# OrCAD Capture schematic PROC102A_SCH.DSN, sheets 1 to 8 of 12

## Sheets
1 12.HARDWARE SCHEMATIC: title: HARDWARE SCHEMATIC; rev: E1
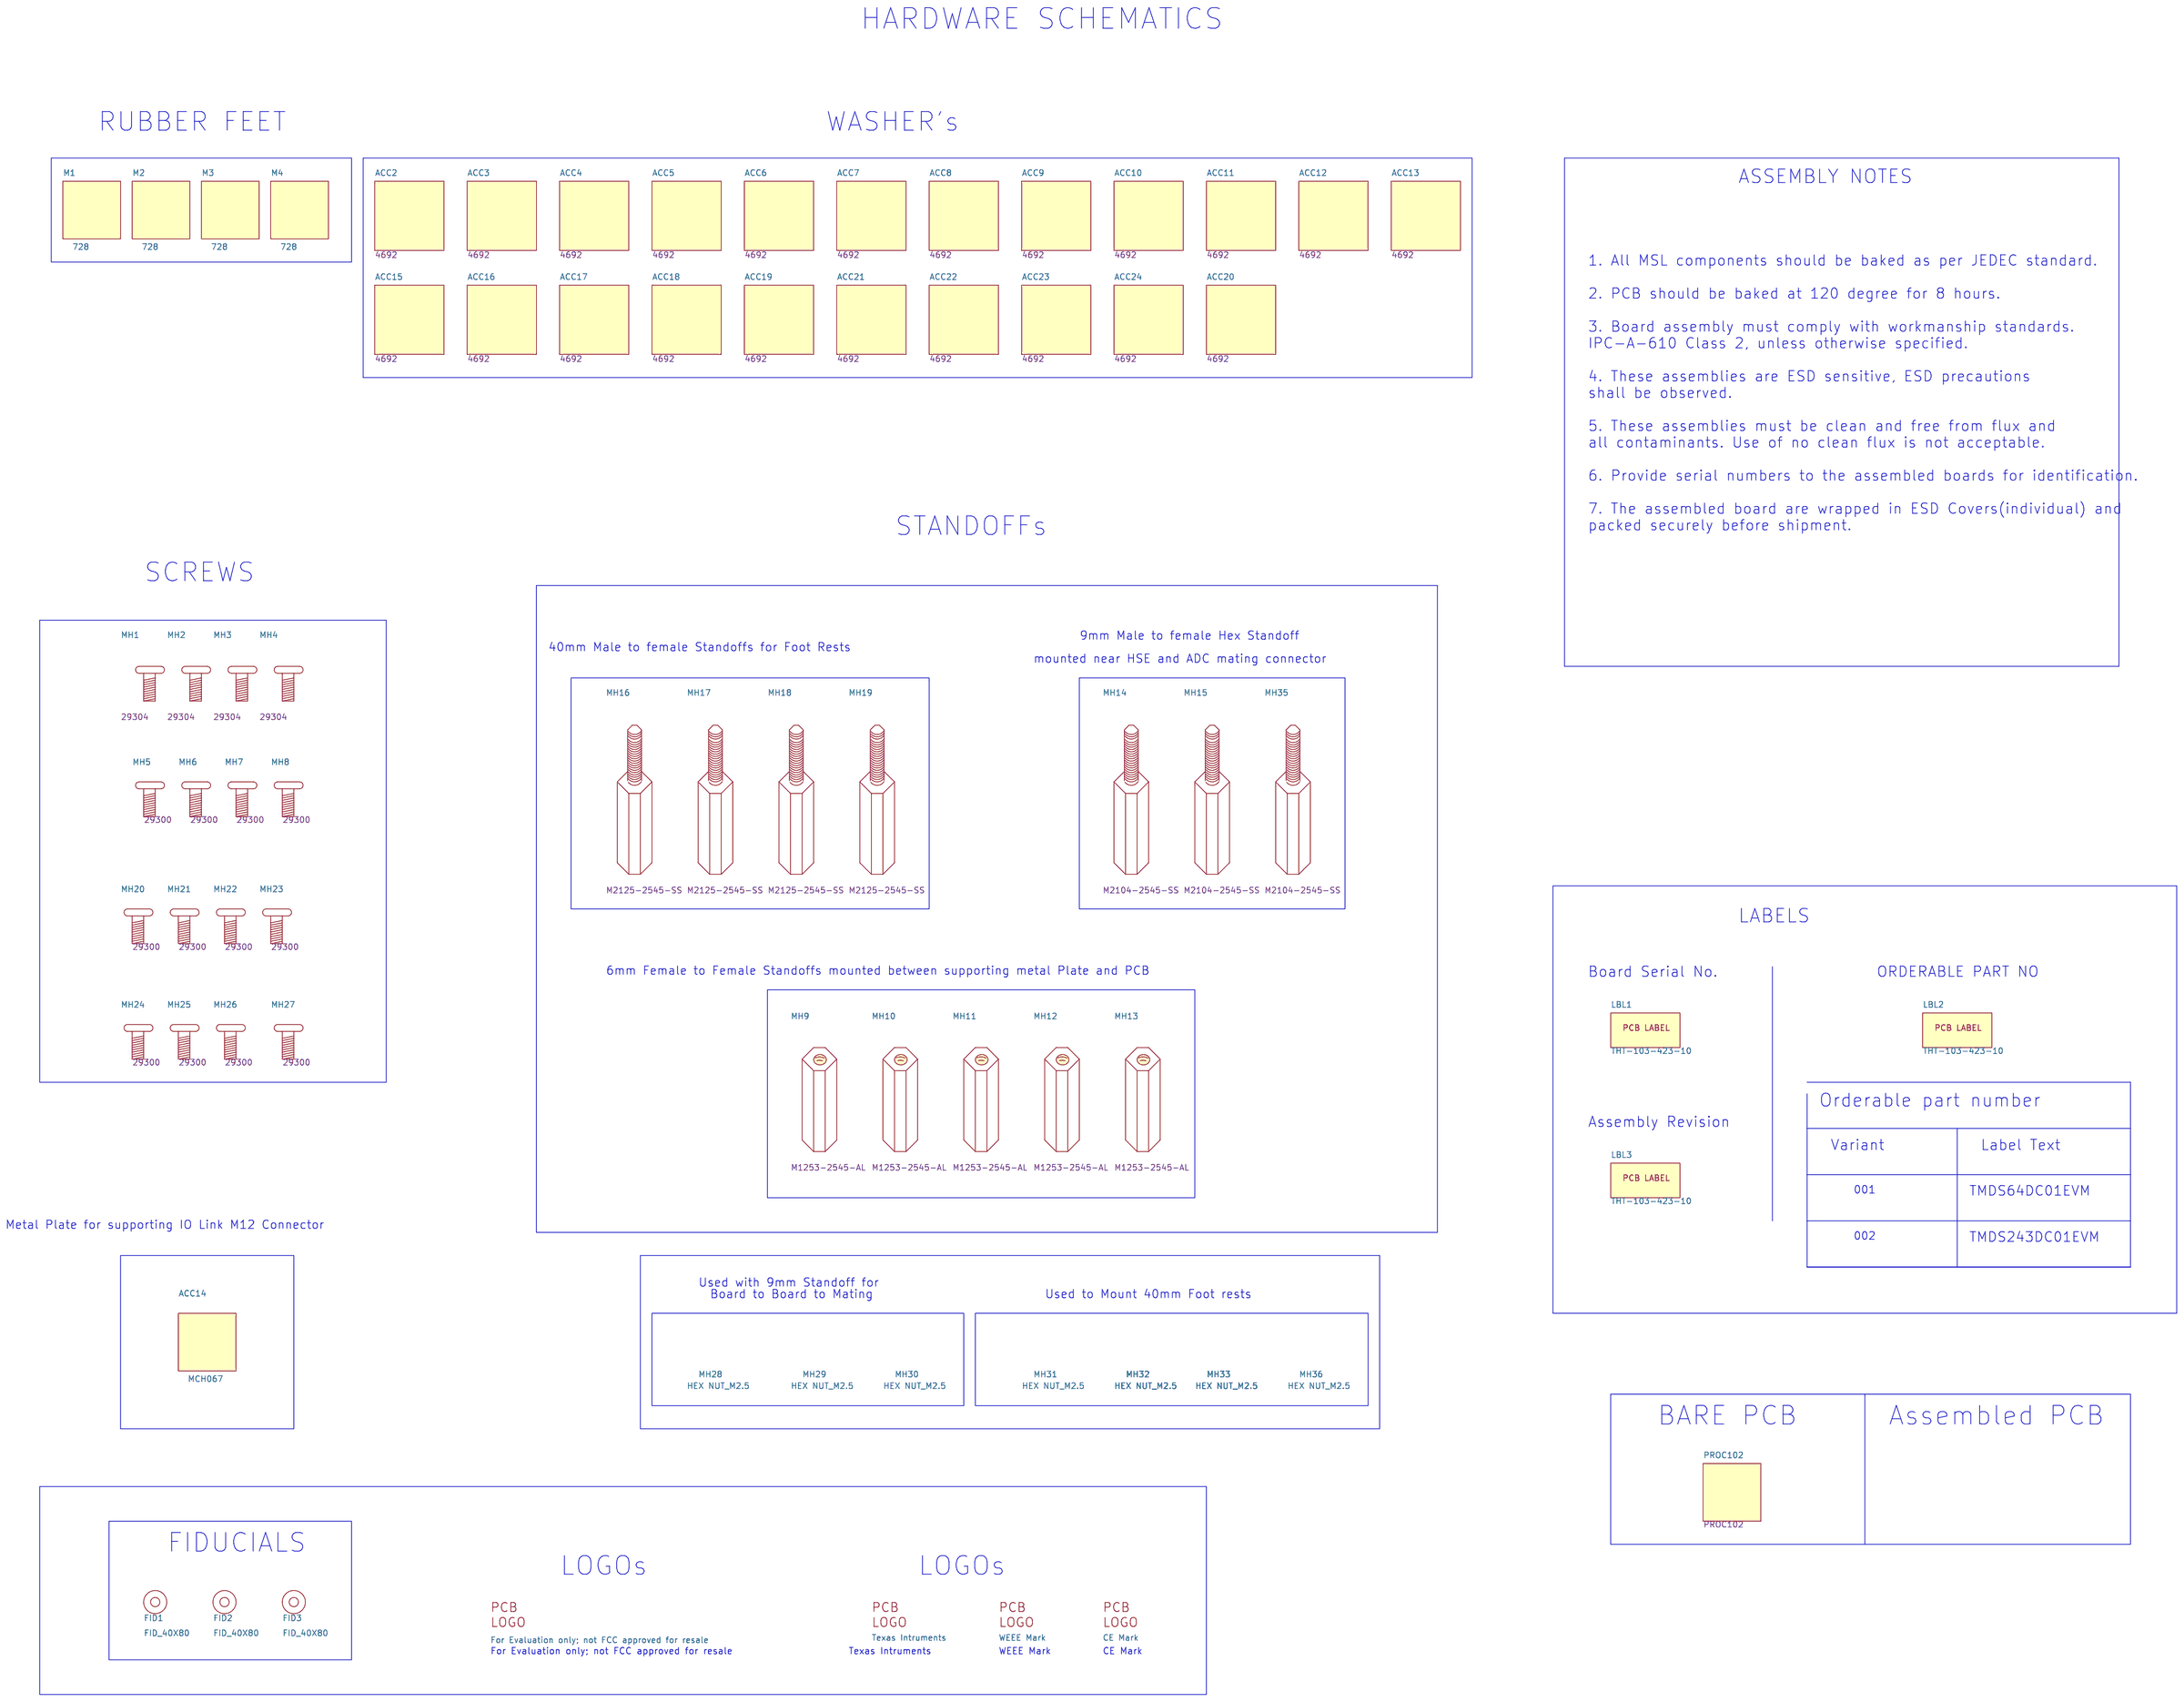
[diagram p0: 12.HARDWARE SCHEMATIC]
2 01.TABLE OF CONTENTS: title: TABLE OF CONTENTS
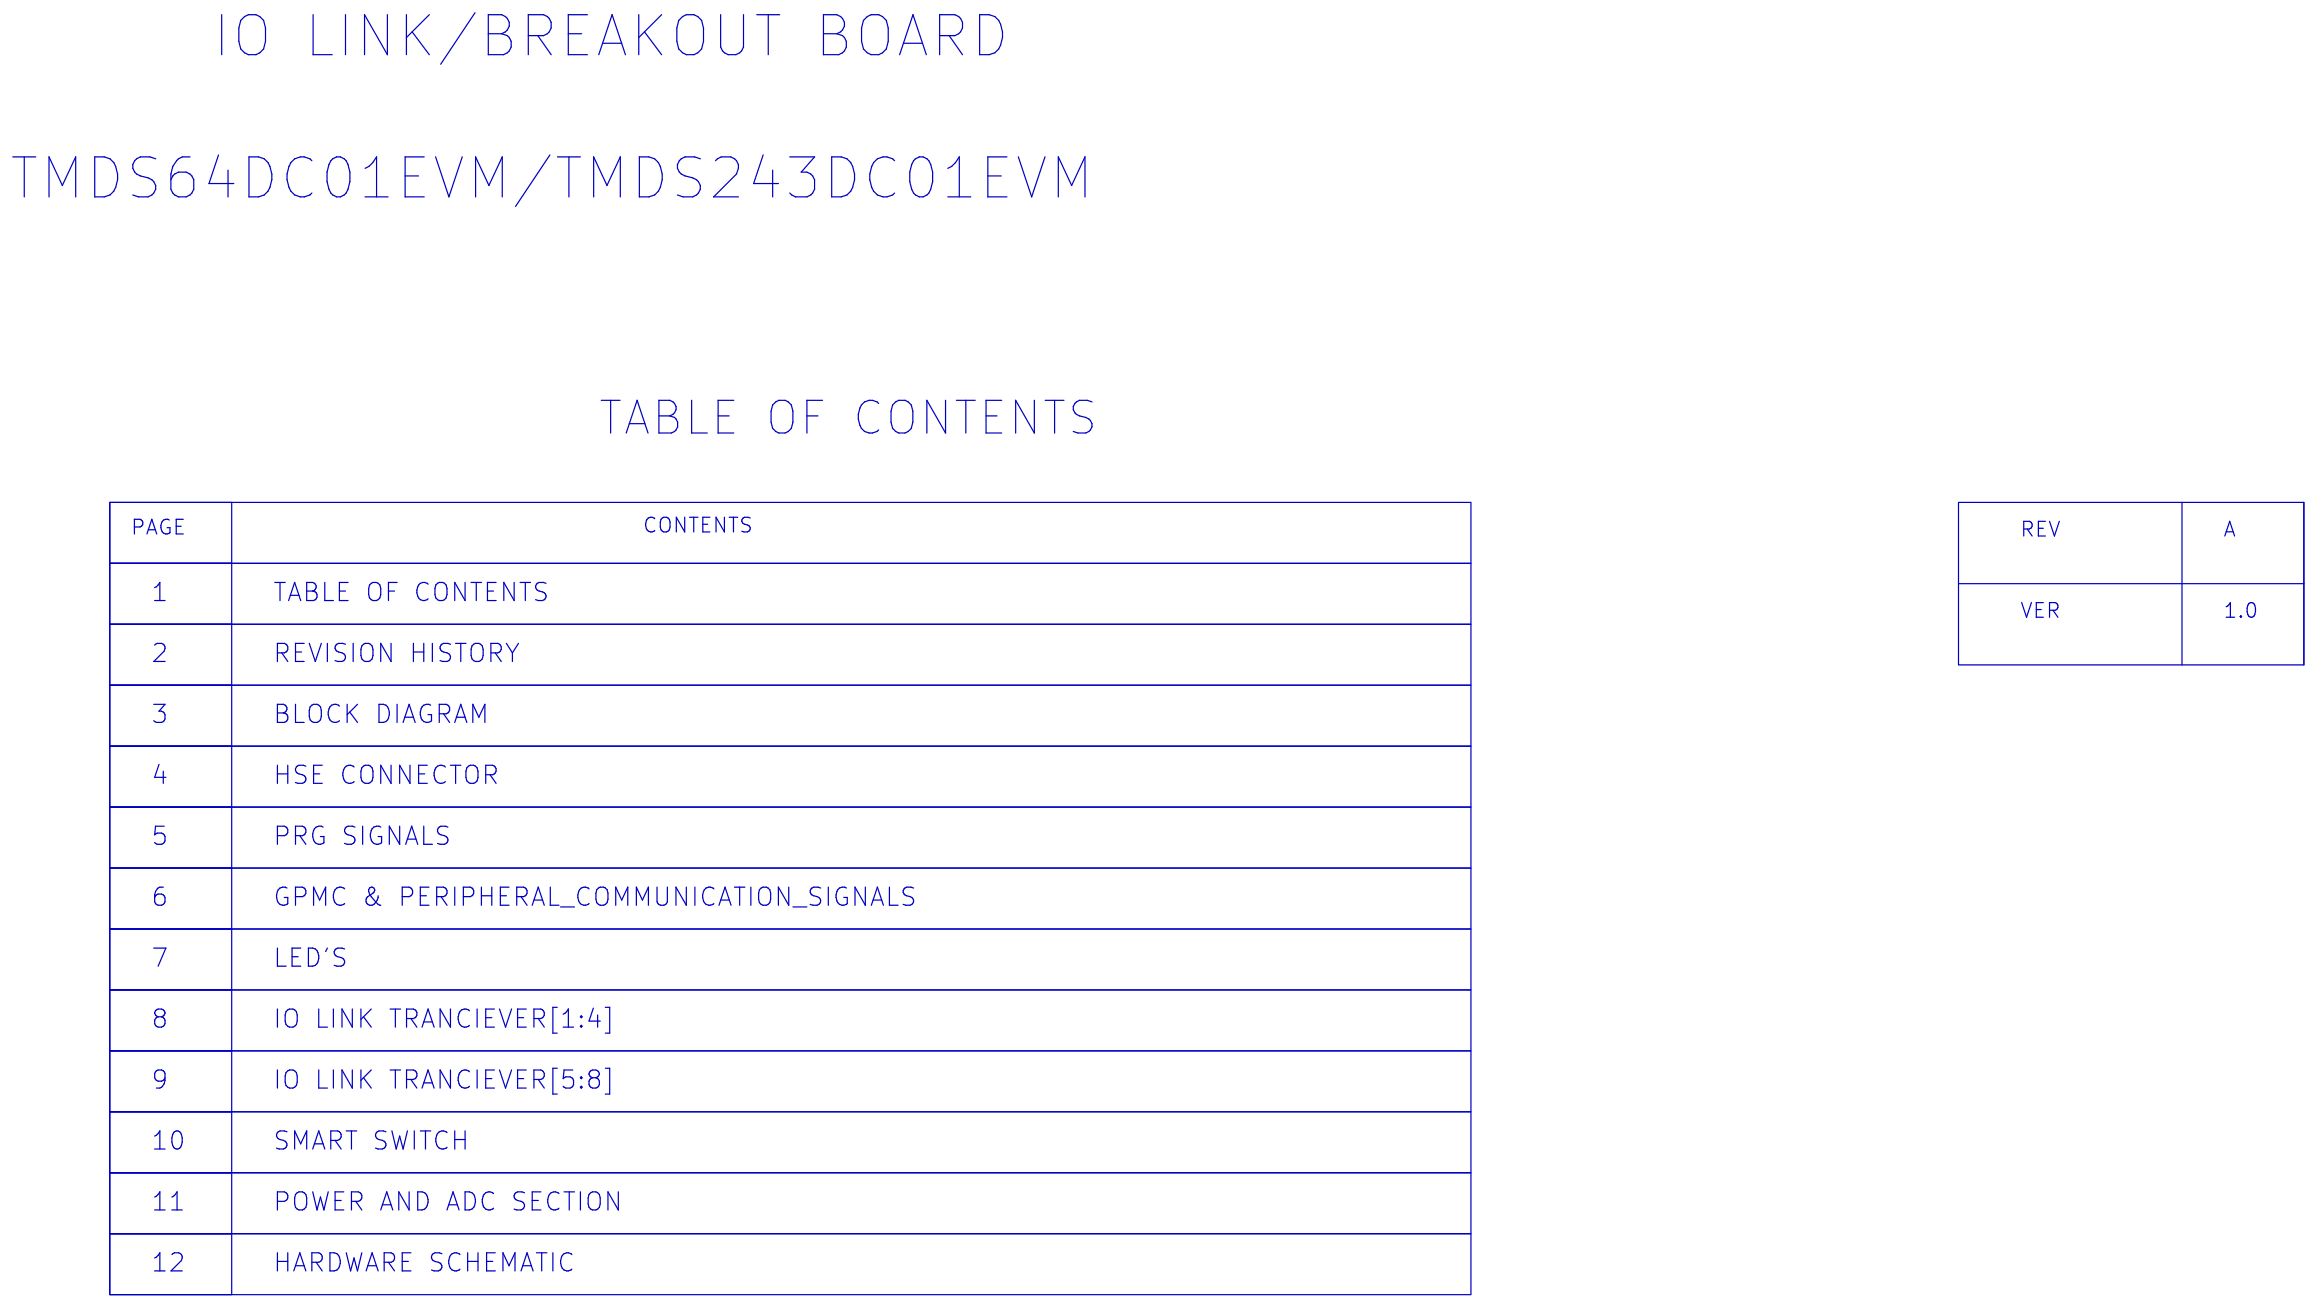
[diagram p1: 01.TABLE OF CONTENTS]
3 02.REVISION HISTORY: title: REV HISTORY
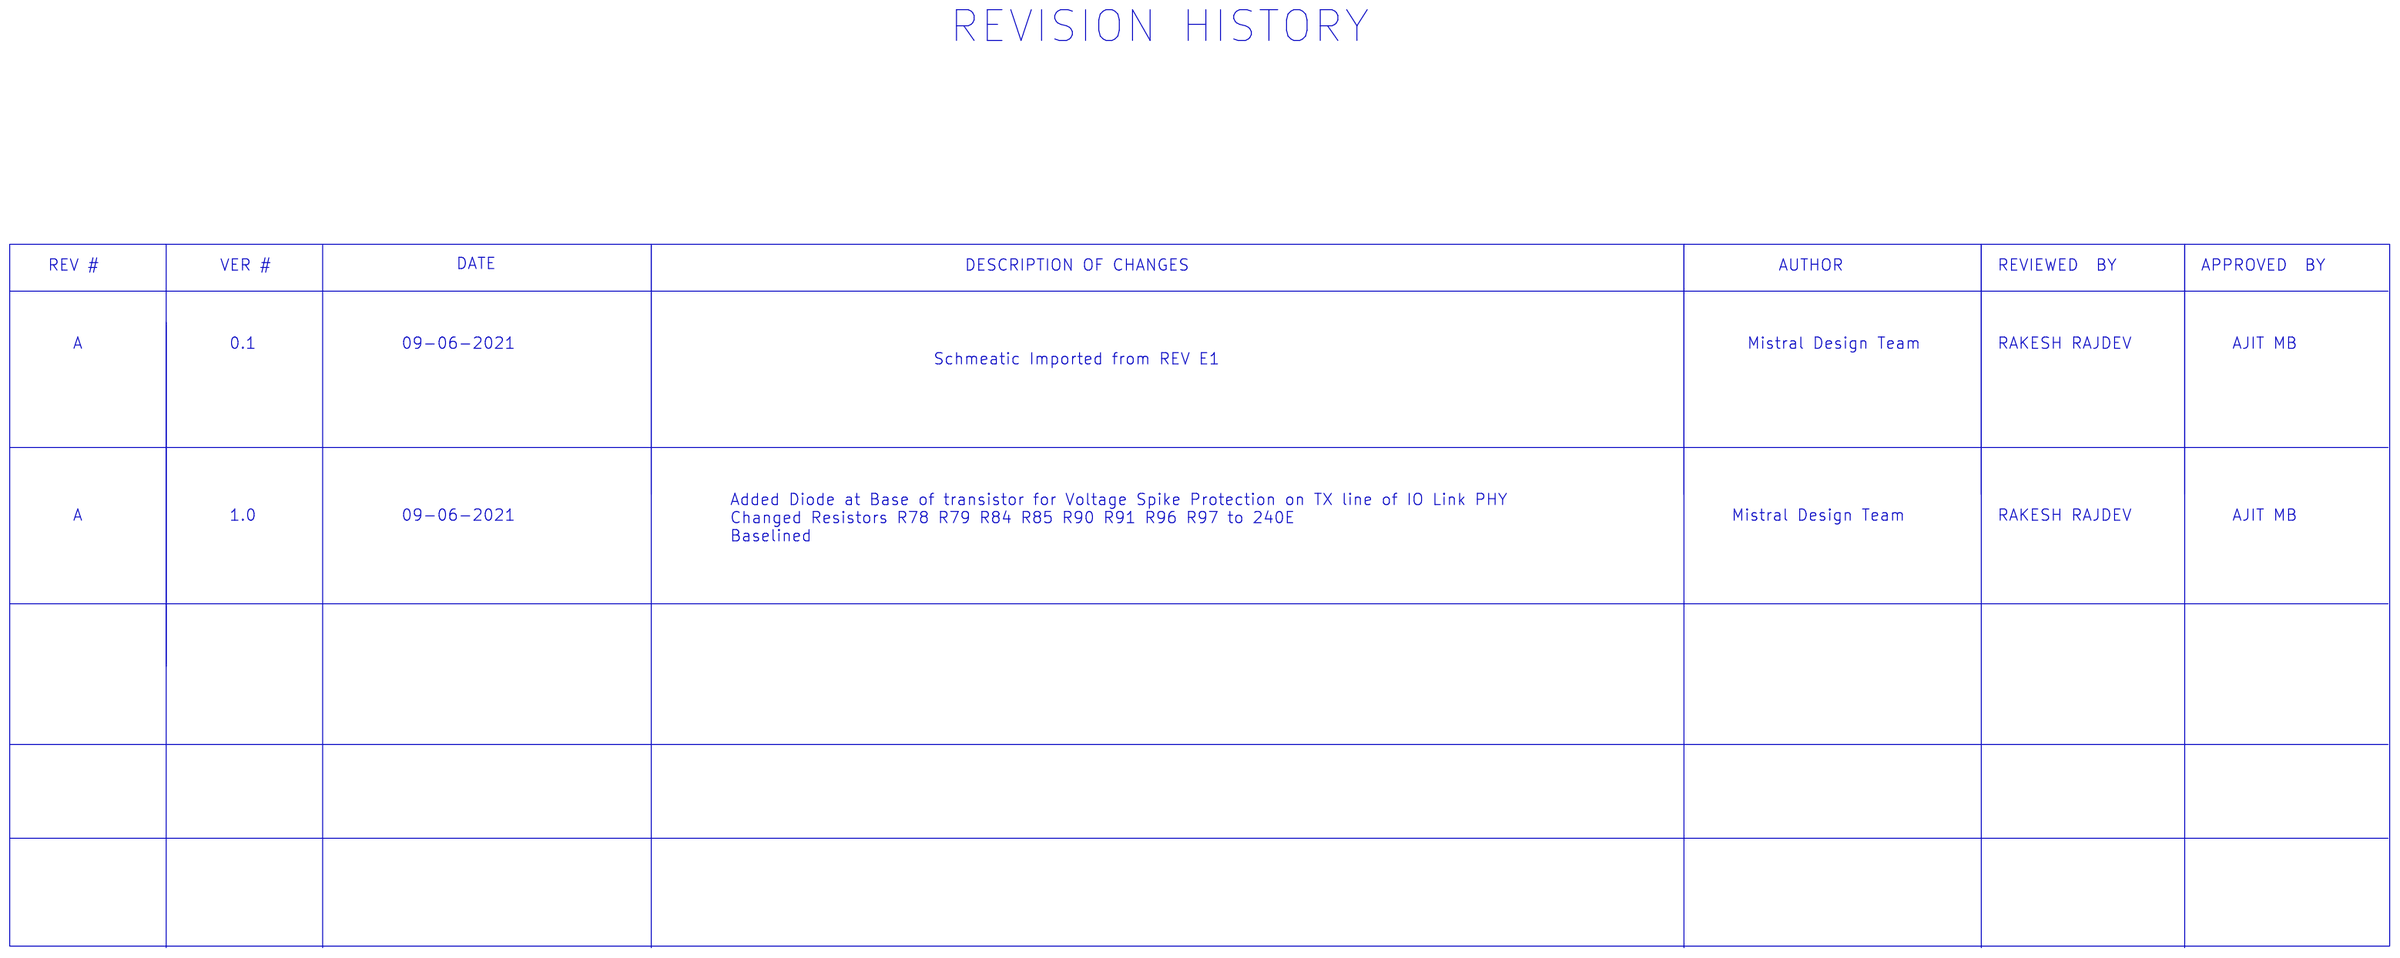
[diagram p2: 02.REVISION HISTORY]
4 03.BLOCK DIAGRAM: title: BLOCK DIAGRAM
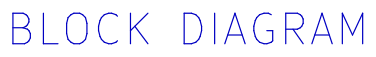
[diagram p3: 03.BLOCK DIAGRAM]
5 04.HSE CONNECTOR: size C; title: HSE CONNECTOR
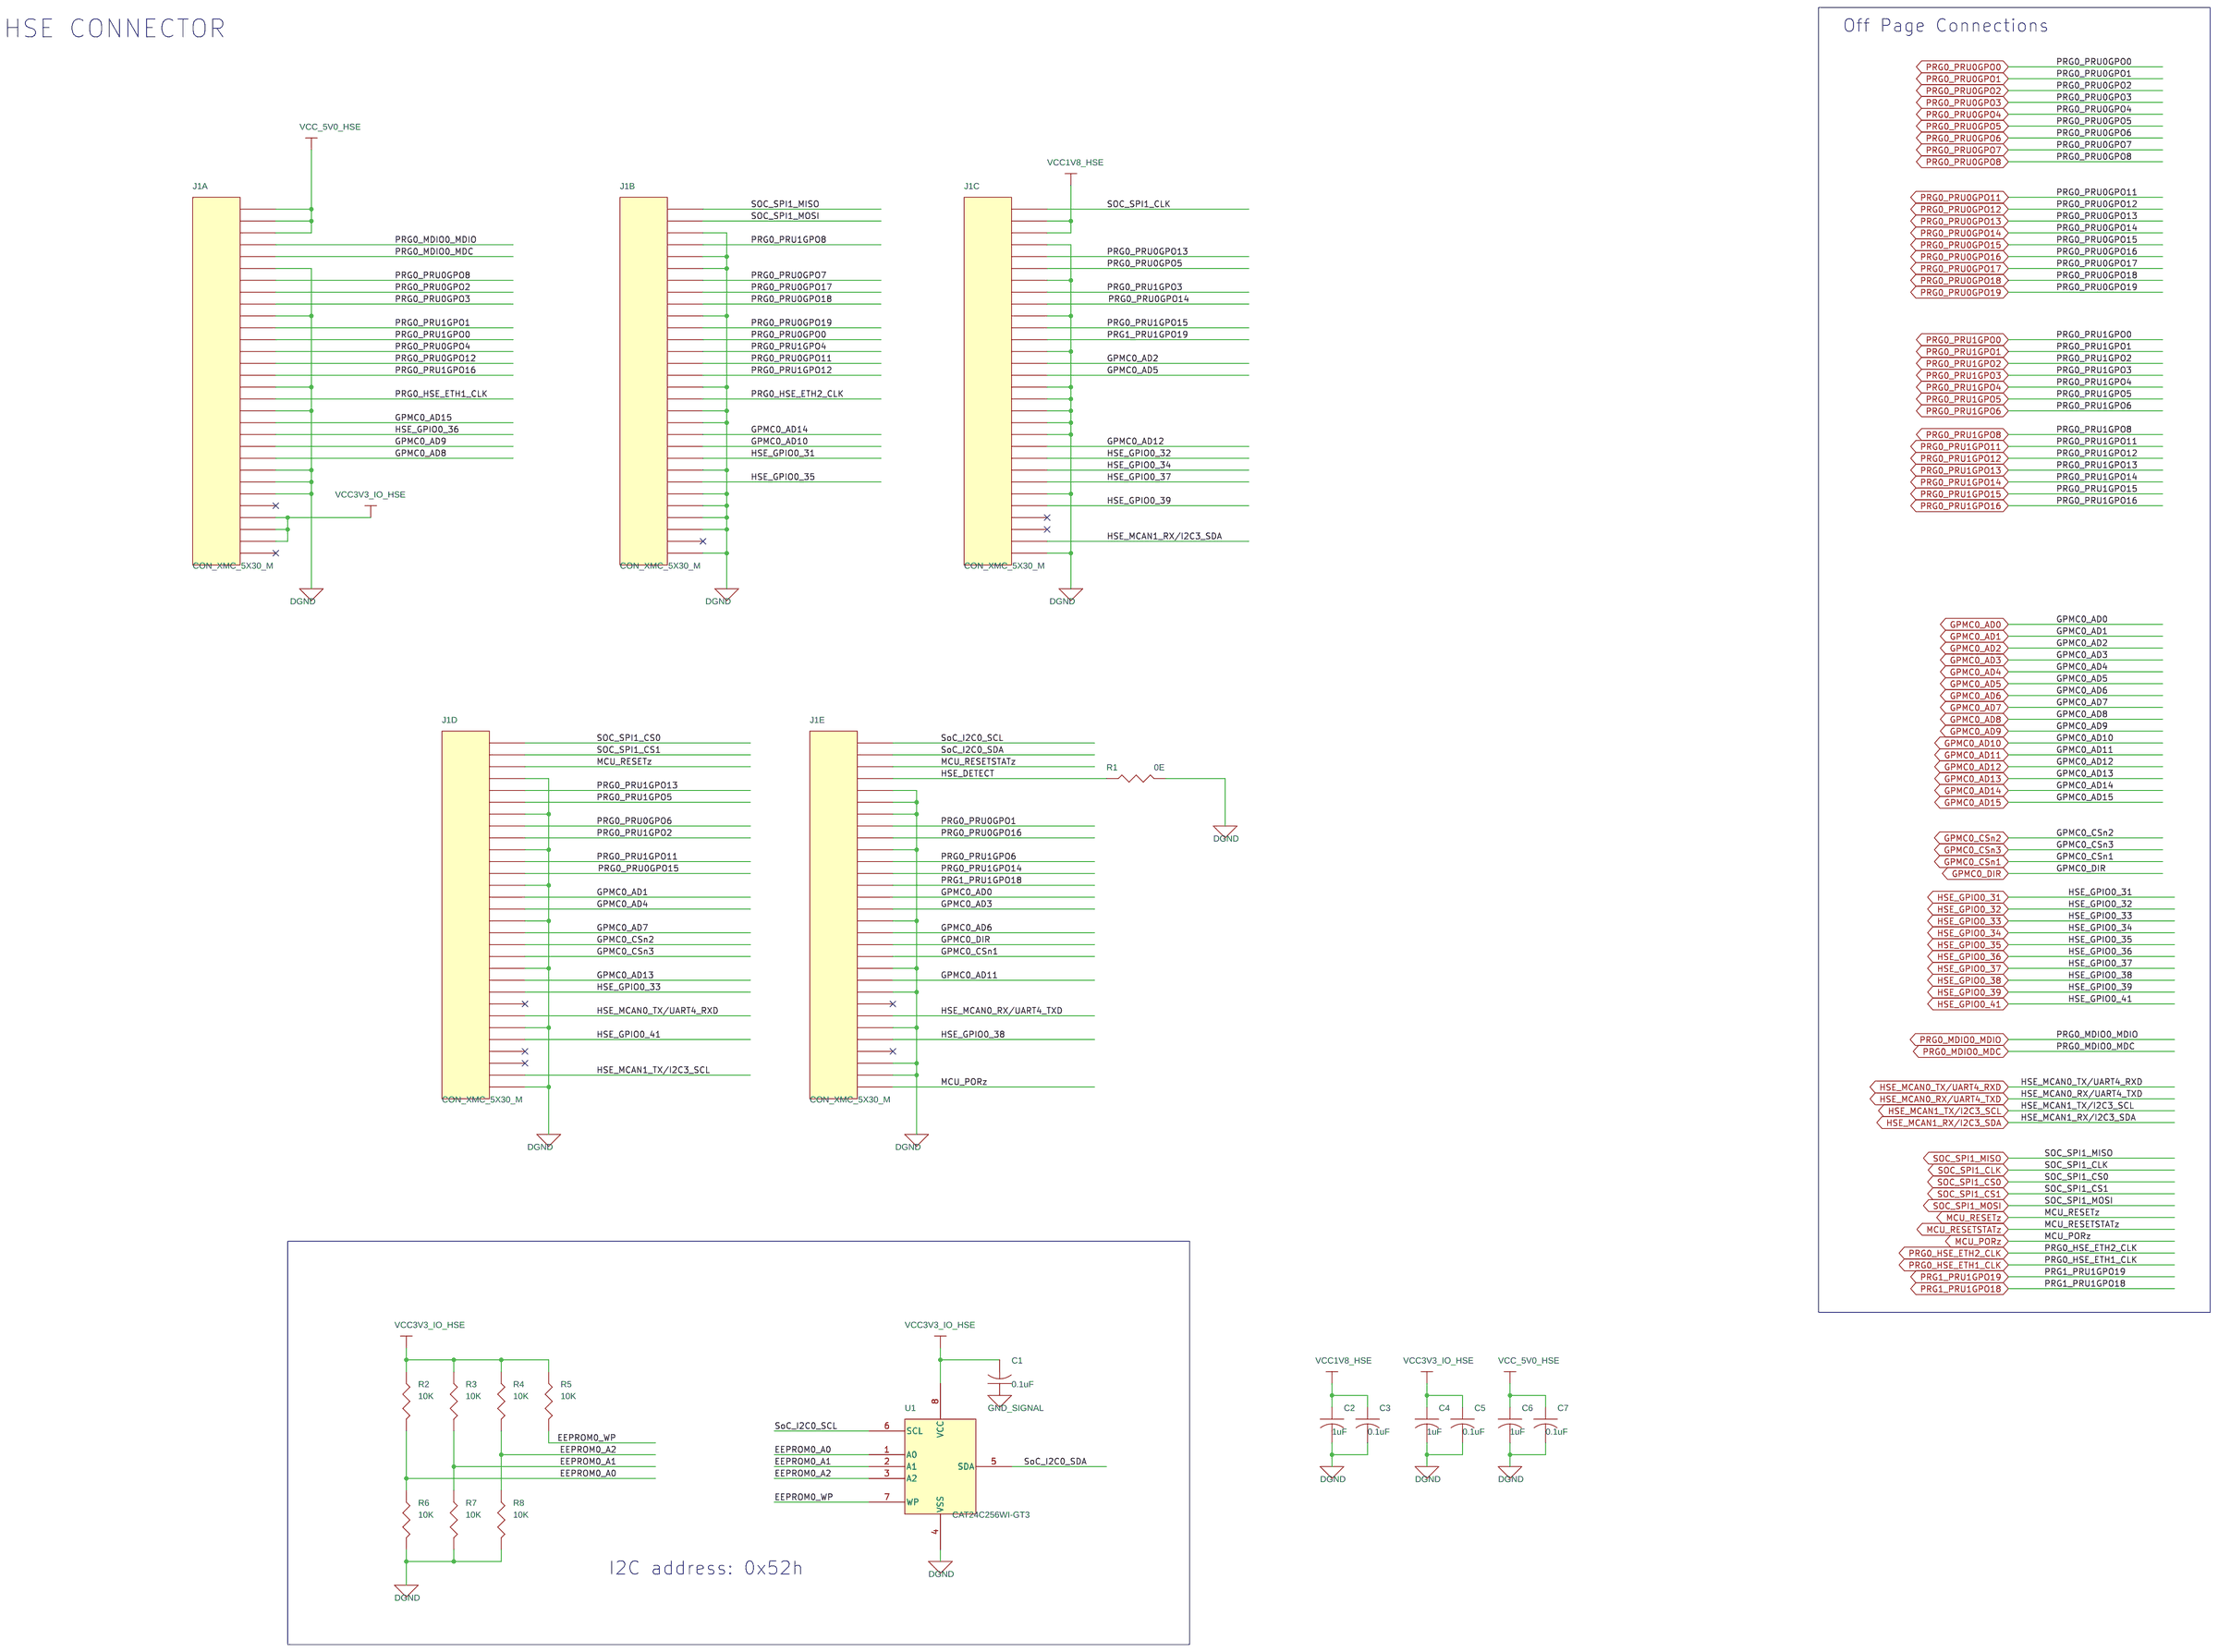
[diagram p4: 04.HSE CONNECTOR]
6 05.PRGO SIGNALS(01): size C; title: PRG SIGNALS
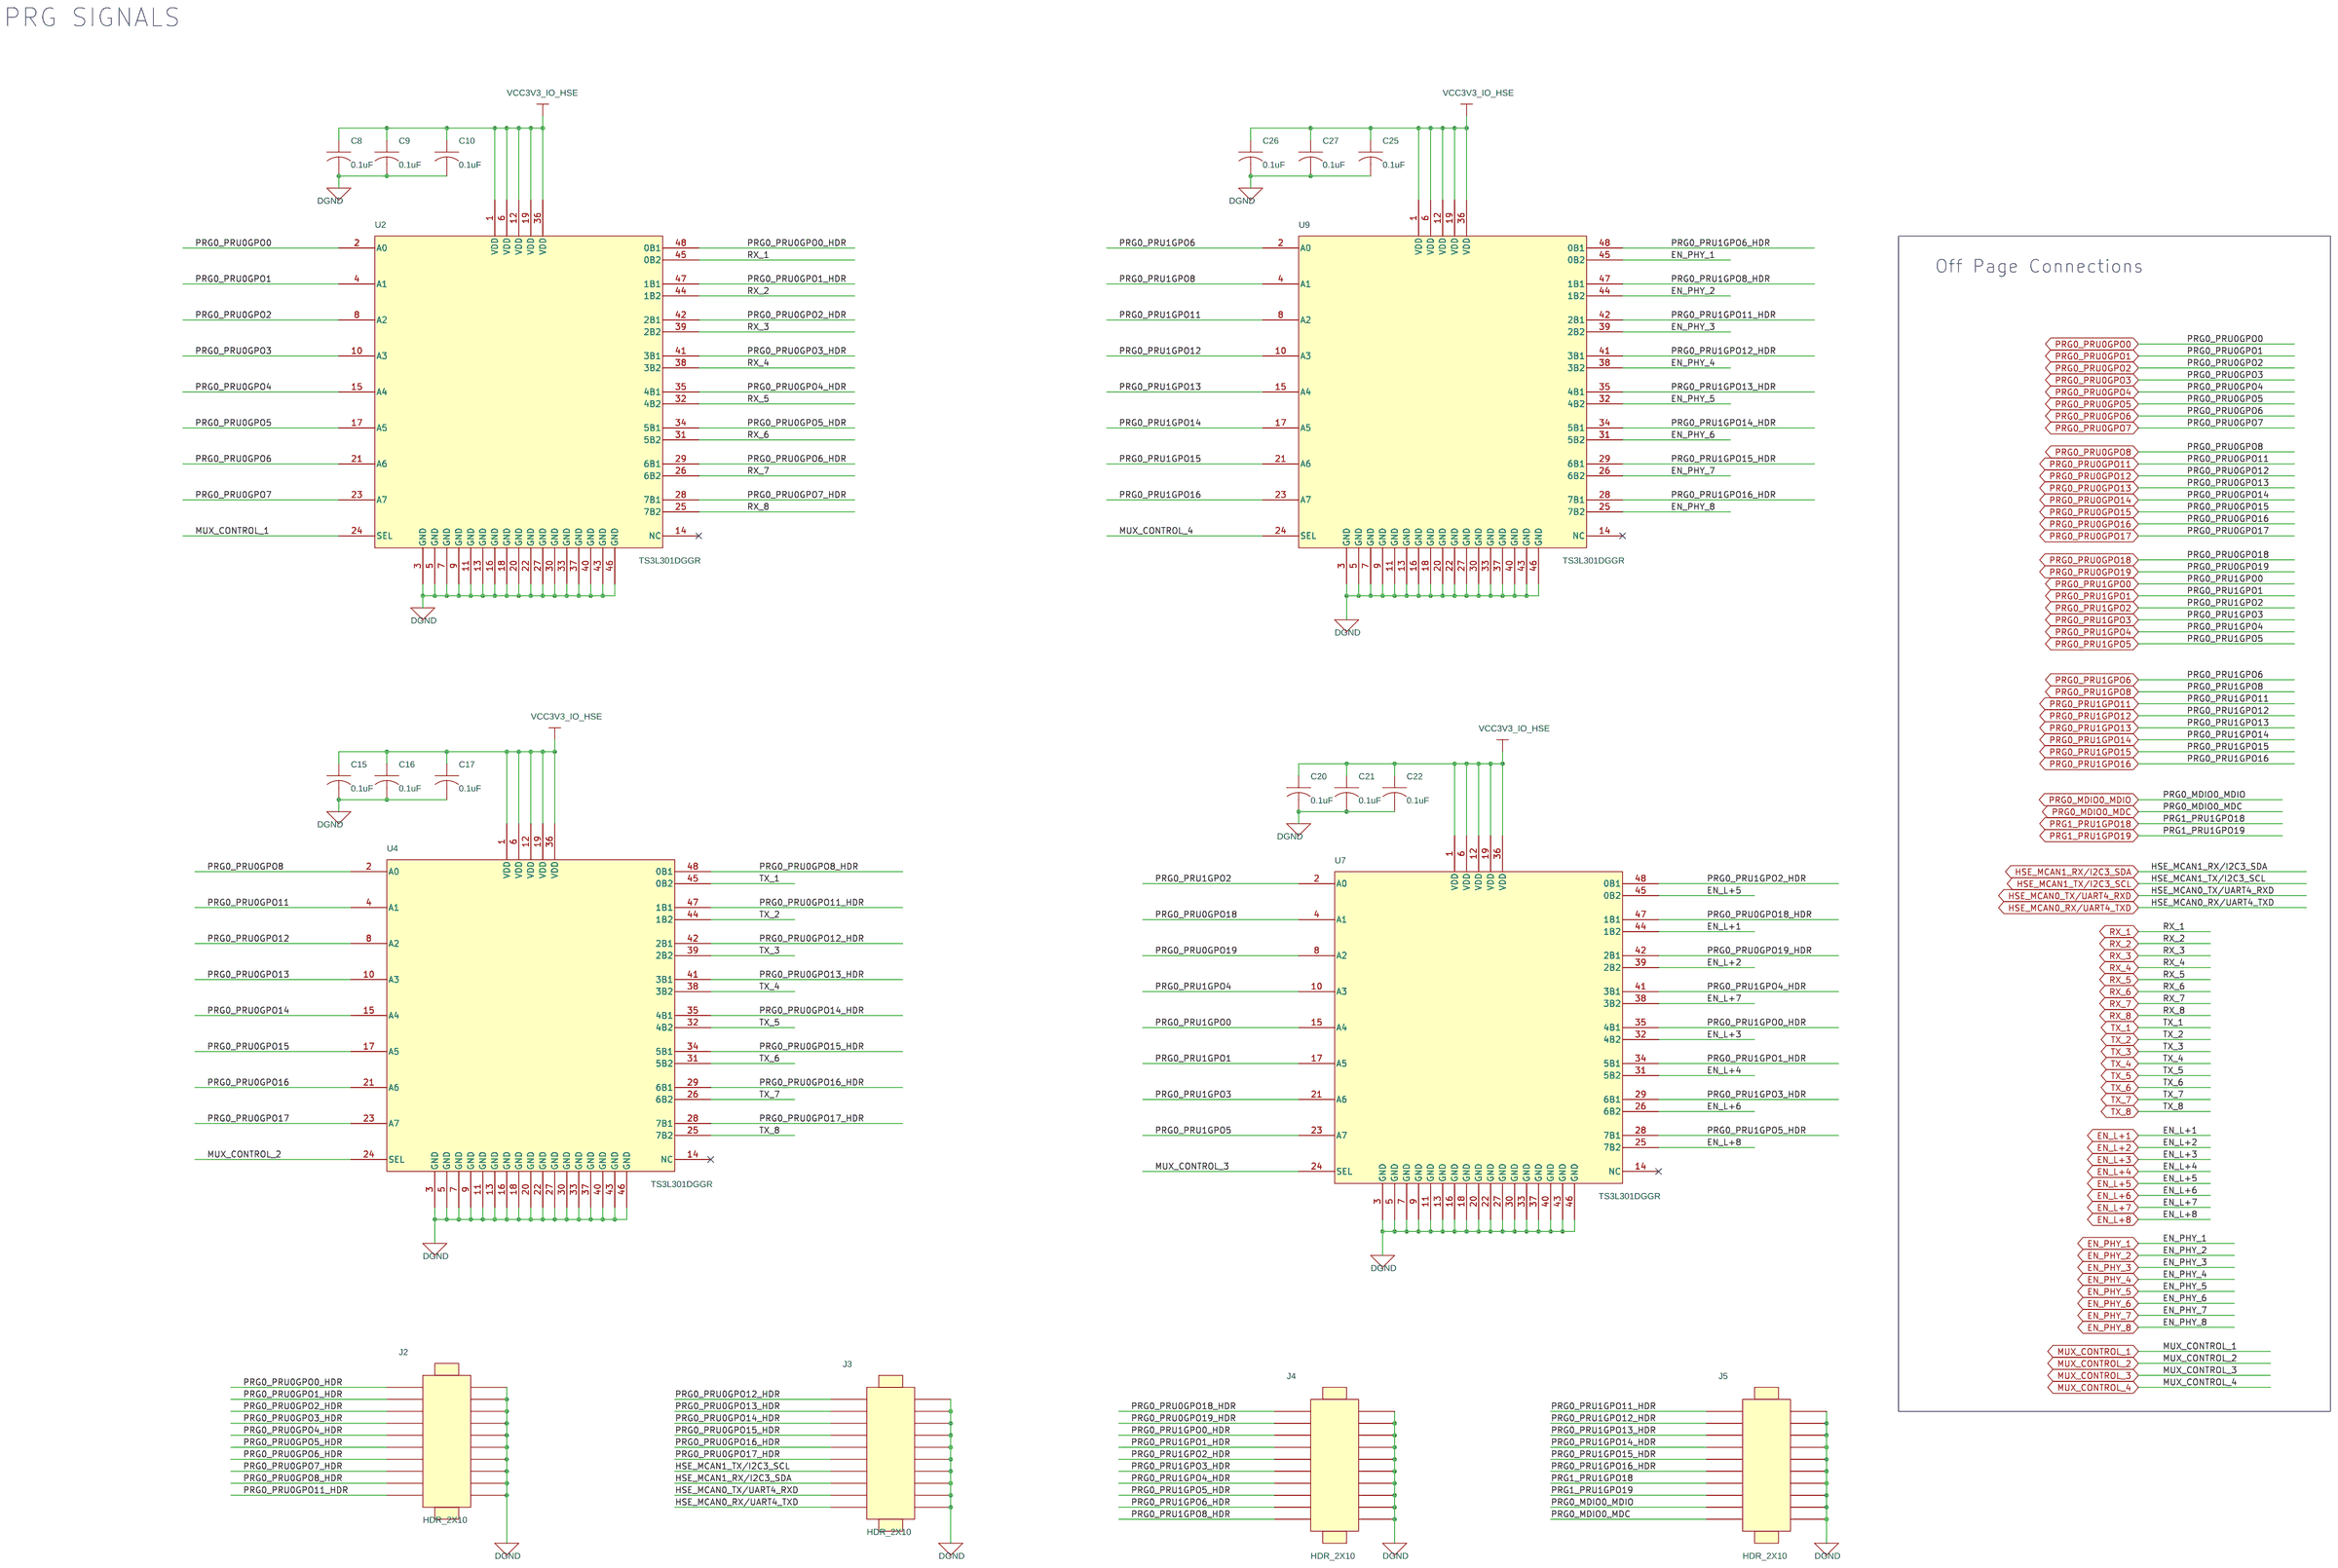
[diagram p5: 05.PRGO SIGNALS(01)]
7 06.PRG0 SIGNAL(02): size C; title: GPMC & PERIPHERAL COMMUNICATION SIGNALS
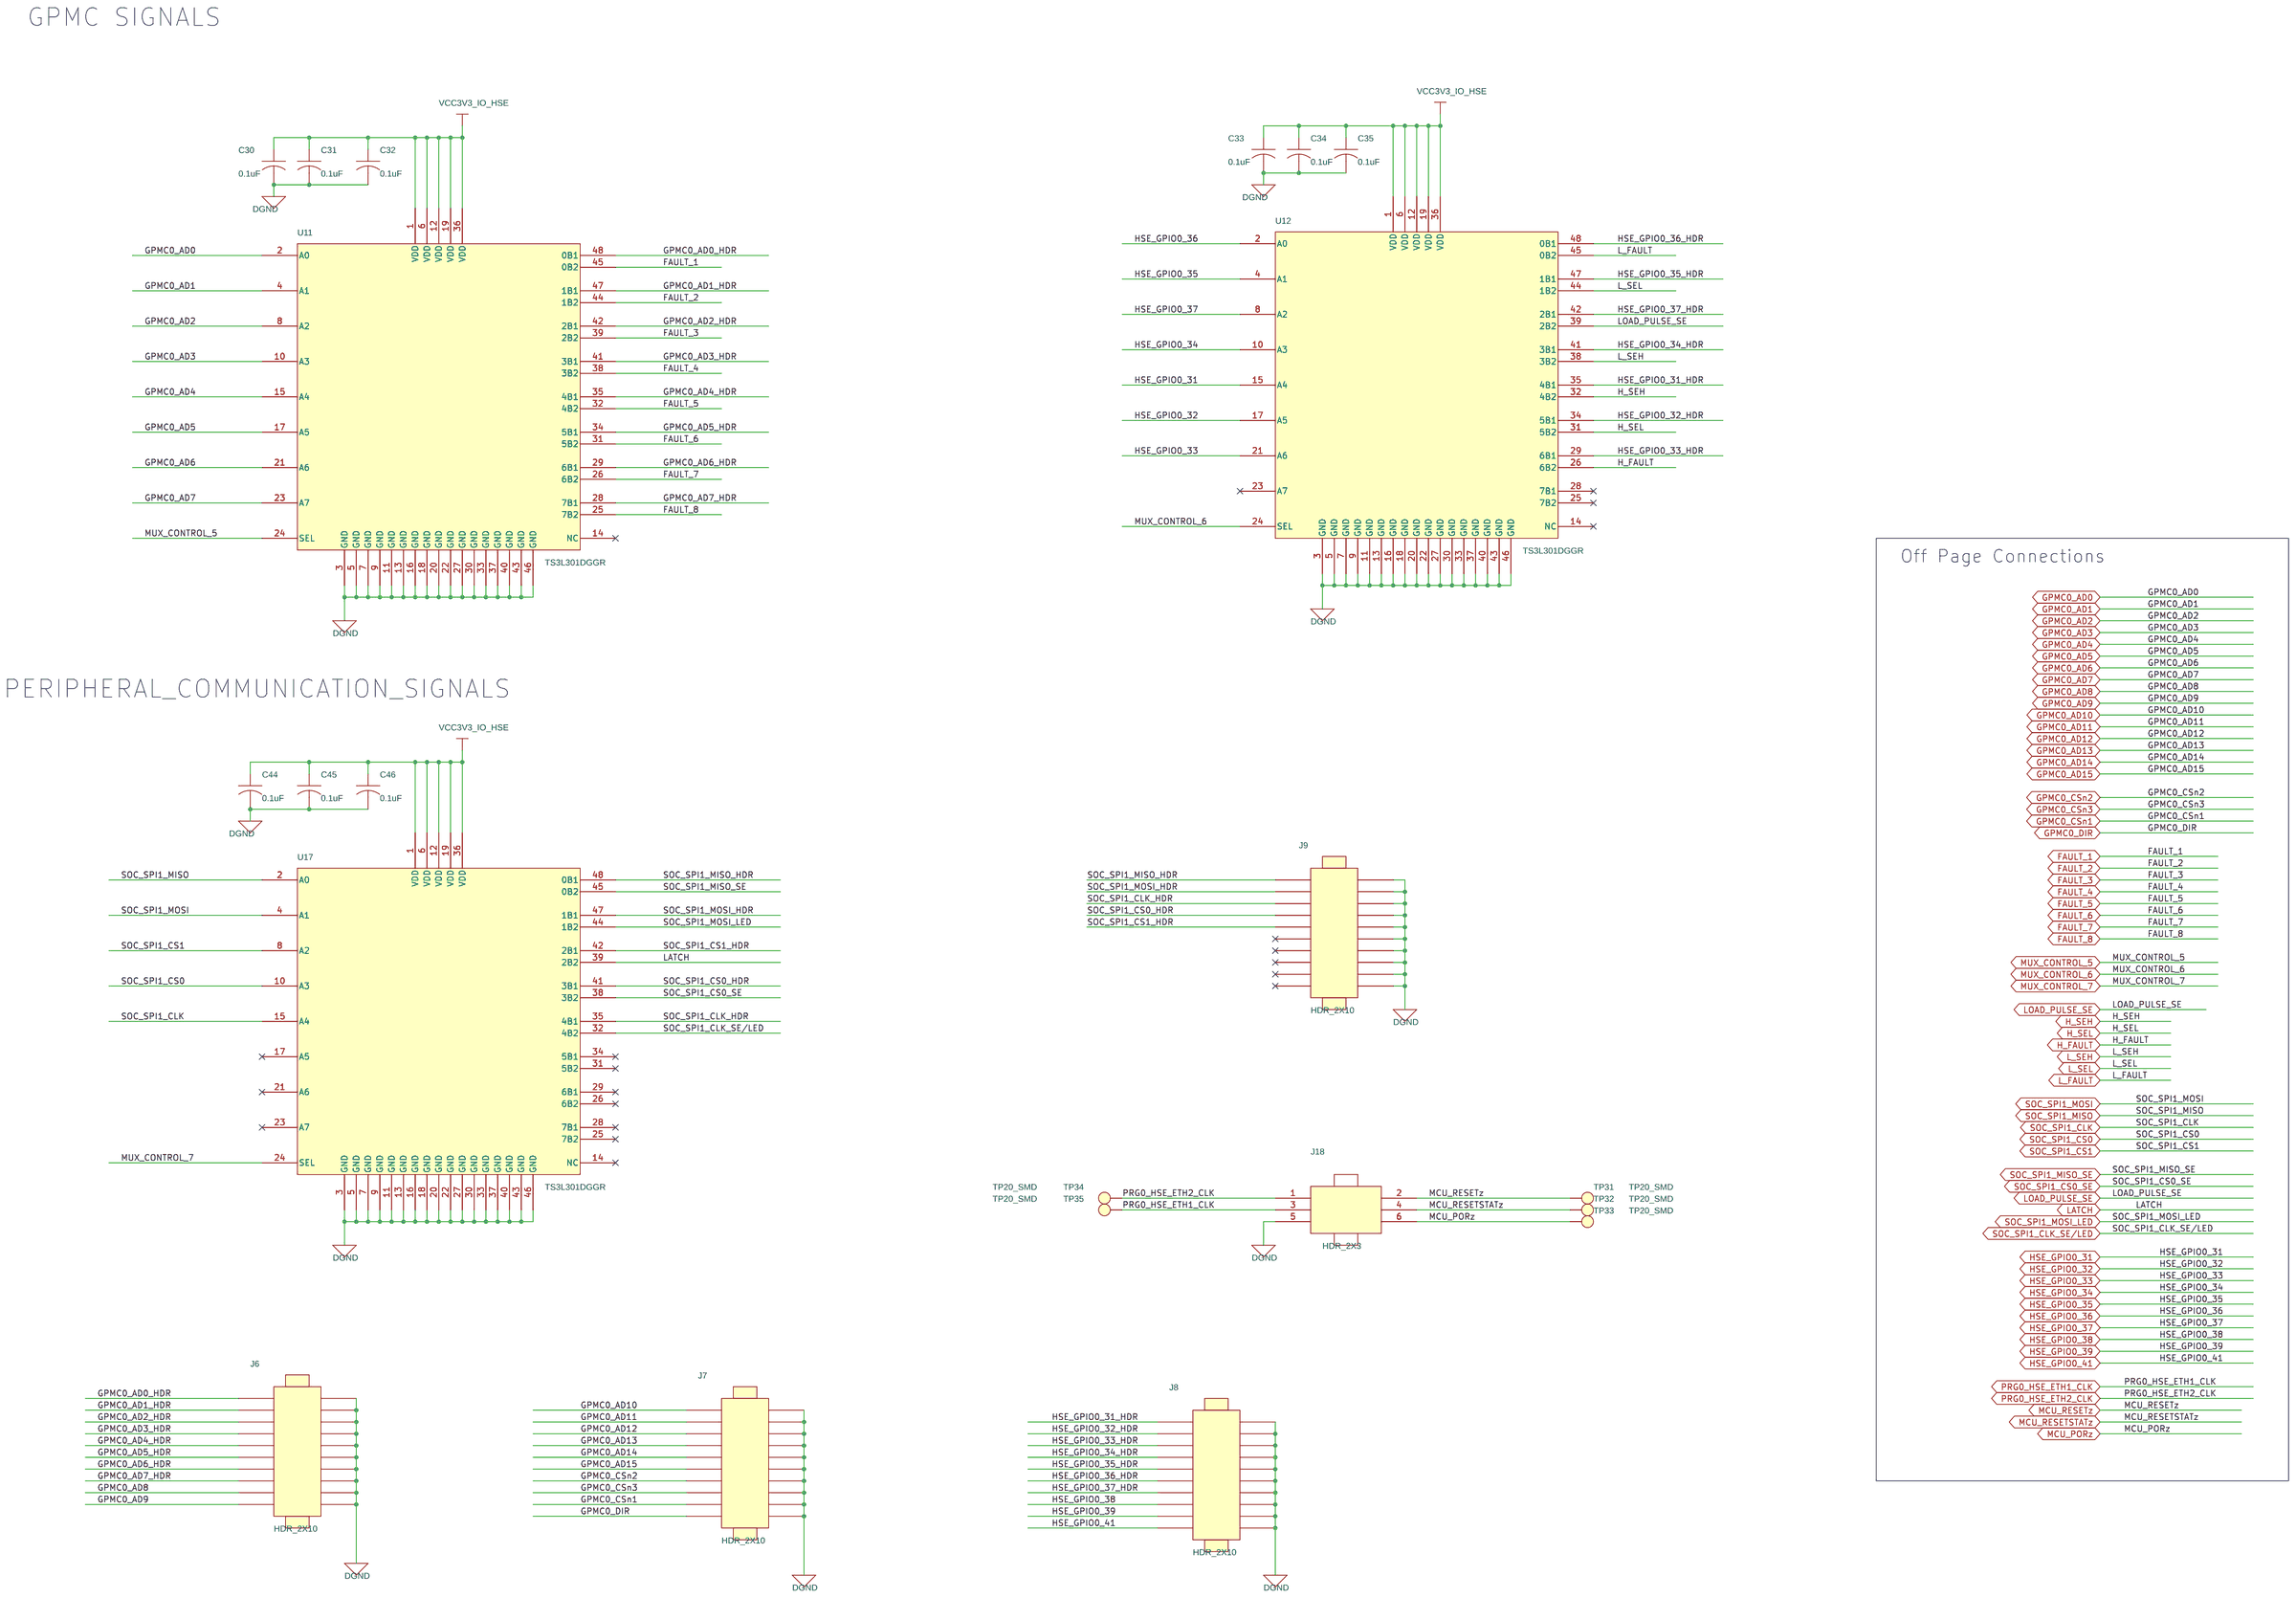
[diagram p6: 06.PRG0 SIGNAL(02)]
8 07.LED: size C; title: LED
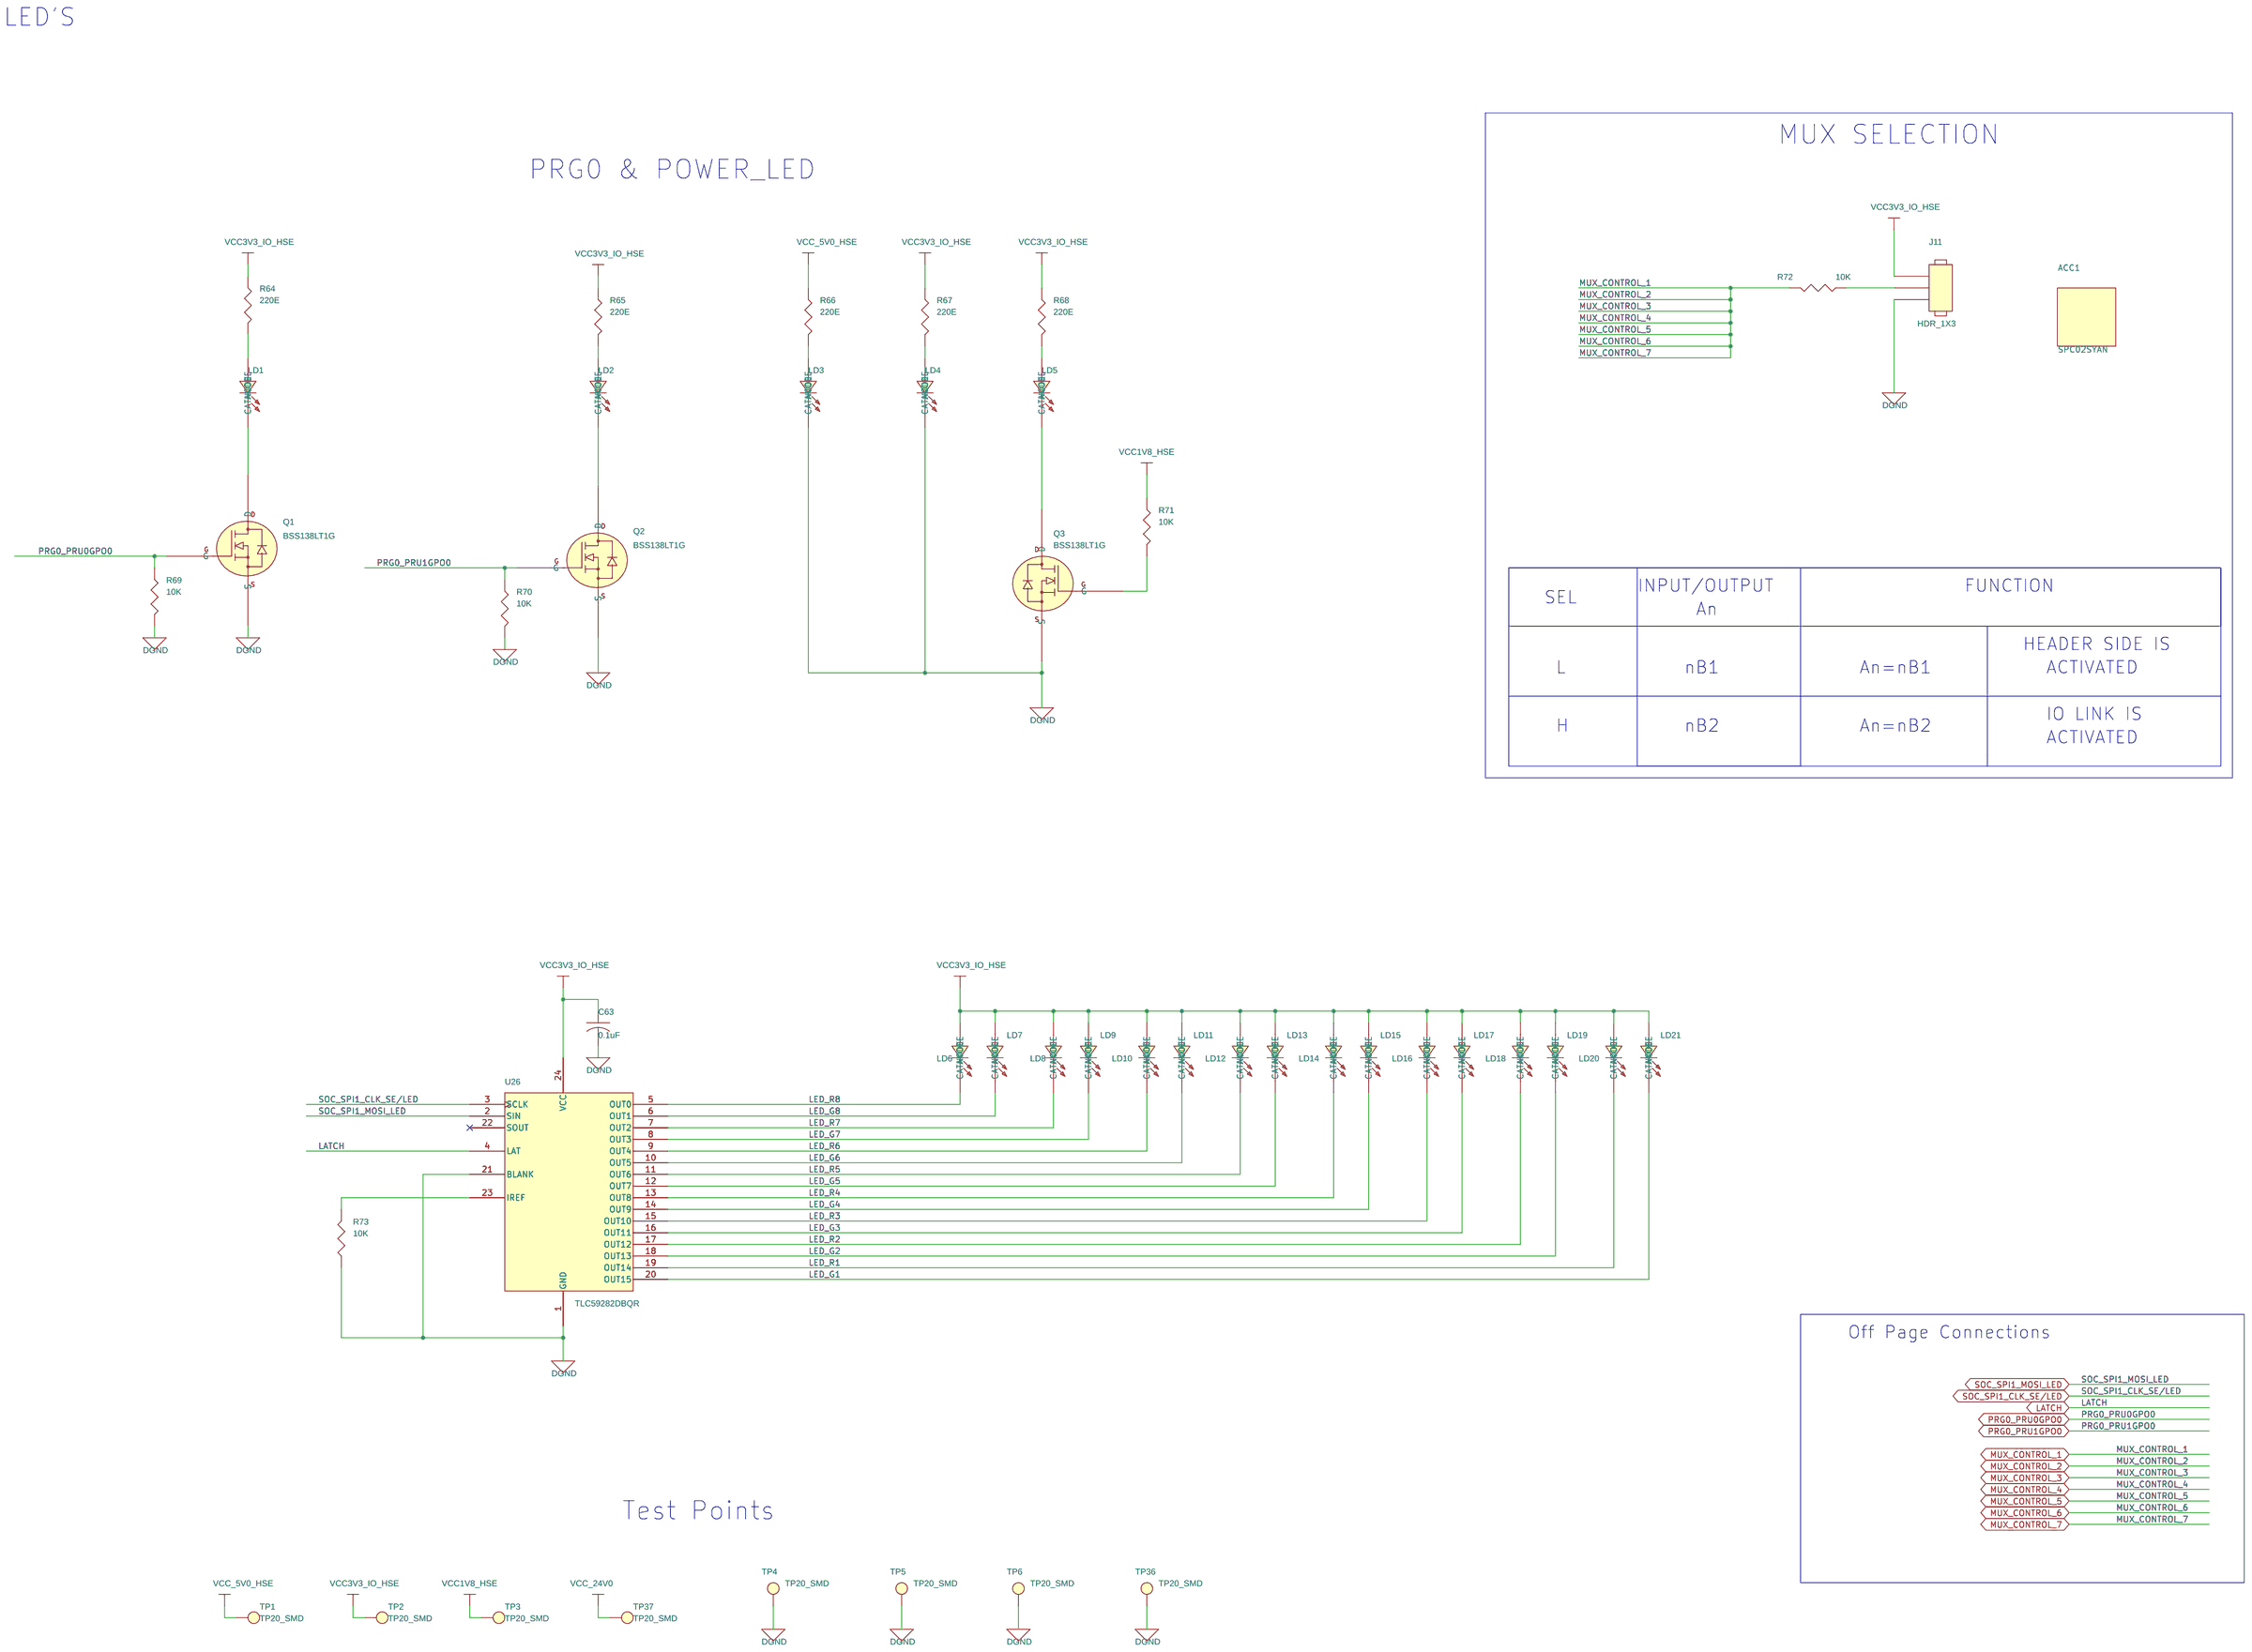
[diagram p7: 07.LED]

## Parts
sheet 04.HSE CONNECTOR
C1  0.1uF  [CAP0402_0-75]
C2  1uF  [CAP0402_0-75]
C3  0.1uF  [CAP0402_0-75]
C4  1uF  [CAP0402_0-75]
C5  0.1uF  [CAP0402_0-75]
C6  1uF  [CAP0402_0-75]
C7  0.1uF  [CAP0402_0-75]
J1  CON_XMC_5X30_M  [CON_XMC5X30_SEAM-30-03-5-05-2-A_P_S_S_7-5]  (sections A,B,C,D,E)
R1  0E  [RES0402_0-5]
R2  10K  [RES0402_0-5]
R3  10K  [RES0402_0-5]
R4  10K  [RES0402_0-5]
R5  10K  [RES0402_0-5]
R6  10K  [RES0402_0-5]
R7  10K  [RES0402_0-5]
R8  10K  [RES0402_0-5]
U1  CAT24C256WI-GT3  [SOIC8_1-8]
sheet 05.PRGO SIGNALS(01)
C8  0.1uF  [CAP0402_0-75]
C9  0.1uF  [CAP0402_0-75]
C10  0.1uF  [CAP0402_0-75]
C15  0.1uF  [CAP0402_0-75]
C16  0.1uF  [CAP0402_0-75]
C17  0.1uF  [CAP0402_0-75]
C20  0.1uF  [CAP0402_0-75]
C21  0.1uF  [CAP0402_0-75]
C22  0.1uF  [CAP0402_0-75]
C25  0.1uF  [CAP0402_0-75]
C26  0.1uF  [CAP0402_0-75]
C27  0.1uF  [CAP0402_0-75]
J2  HDR_2X10  [HDR_2X10_TSW_100_S_T]
J3  HDR_2X10  [HDR_2X10_TSW_100_S_T]
J4  HDR_2X10  [HDR_2X10_TSW_100_S_T]
J5  HDR_2X10  [HDR_2X10_TSW_100_S_T]
U2  TS3L301DGGR  [TSSOP48_19-68_500X245_1-2]
U4  TS3L301DGGR  [TSSOP48_19-68_500X245_1-2]
U7  TS3L301DGGR  [TSSOP48_19-68_500X245_1-2]
U9  TS3L301DGGR  [TSSOP48_19-68_500X245_1-2]
sheet 06.PRG0 SIGNAL(02)
C30  0.1uF  [CAP0402_0-75]
C31  0.1uF  [CAP0402_0-75]
C32  0.1uF  [CAP0402_0-75]
C33  0.1uF  [CAP0402_0-75]
C34  0.1uF  [CAP0402_0-75]
C35  0.1uF  [CAP0402_0-75]
C44  0.1uF  [CAP0402_0-75]
C45  0.1uF  [CAP0402_0-75]
C46  0.1uF  [CAP0402_0-75]
J6  HDR_2X10  [HDR_2X10_TSW_100_S_T]
J7  HDR_2X10  [HDR_2X10_TSW_100_S_T]
J8  HDR_2X10  [HDR_2X10_TSW_100_S_T]
J9  HDR_2X10  [HDR_2X10_TSW_100_S_T]
J18  HDR_2X3  [HDR_2X3_TSW-103-07-D_S_T_8-4]
TP31  TP20_SMD  [TP20_SMD]
TP32  TP20_SMD  [TP20_SMD]
TP33  TP20_SMD  [TP20_SMD]
TP34  TP20_SMD  [TP20_SMD]
TP35  TP20_SMD  [TP20_SMD]
U11  TS3L301DGGR  [TSSOP48_19-68_500X245_1-2]
U12  TS3L301DGGR  [TSSOP48_19-68_500X245_1-2]
U17  TS3L301DGGR  [TSSOP48_19-68_500X245_1-2]
sheet 07.LED
ACC1  SPC02SYAN  [NA]
C63  0.1uF  [CAP0402_0-75]
J11  HDR_1X3  [HDR_3X1_100_S_T]
LD1  150060VS75000  [LED_150060SS75000_70X40_SMD_0-8]
LD2  150060VS75000  [LED_150060SS75000_70X40_SMD_0-8]
LD3  150060VS75000  [LED_150060SS75000_70X40_SMD_0-8]
LD4  150060VS75000  [LED_150060SS75000_70X40_SMD_0-8]
LD5  150060VS75000  [LED_150060SS75000_70X40_SMD_0-8]
LD6  150060RS55040  [LED_150060RS55040_70X40_SMD_0-5]
LD7  150060VS75000  [LED_150060SS75000_70X40_SMD_0-8]
LD8  150060RS55040  [LED_150060RS55040_70X40_SMD_0-5]
LD9  150060VS75000  [LED_150060SS75000_70X40_SMD_0-8]
LD10  150060RS55040  [LED_150060RS55040_70X40_SMD_0-5]
LD11  150060VS75000  [LED_150060SS75000_70X40_SMD_0-8]
LD12  150060RS55040  [LED_150060RS55040_70X40_SMD_0-5]
LD13  150060VS75000  [LED_150060SS75000_70X40_SMD_0-8]
LD14  150060RS55040  [LED_150060RS55040_70X40_SMD_0-5]
LD15  150060VS75000  [LED_150060SS75000_70X40_SMD_0-8]
LD16  150060RS55040  [LED_150060RS55040_70X40_SMD_0-5]
LD17  150060VS75000  [LED_150060SS75000_70X40_SMD_0-8]
LD18  150060RS55040  [LED_150060RS55040_70X40_SMD_0-5]
LD19  150060VS75000  [LED_150060SS75000_70X40_SMD_0-8]
LD20  150060RS55040  [LED_150060RS55040_70X40_SMD_0-5]
LD21  150060VS75000  [LED_150060SS75000_70X40_SMD_0-8]
Q1  BSS138LT1G  [SOT23-123_1-2]
Q2  BSS138LT1G  [SOT23-123_1-2]
Q3  BSS138LT1G  [SOT23-123_1-2]
R64  220E  [RES0402_0-5]
R65  220E  [RES0402_0-5]
R66  220E  [RES0402_0-5]
R67  220E  [RES0402_0-5]
R68  220E  [RES0402_0-5]
R69  10K  [RES0402_0-5]
R70  10K  [RES0402_0-5]
R71  10K  [RES0402_0-5]
R72  10K  [RES0402_0-5]
R73  10K  [RES0402_0-5]
TP1  TP20_SMD  [TP20_SMD]
TP2  TP20_SMD  [TP20_SMD]
TP3  TP20_SMD  [TP20_SMD]
TP4  TP20_SMD  [TP20_SMD]
TP5  TP20_SMD  [TP20_SMD]
TP6  TP20_SMD  [TP20_SMD]
TP36  TP20_SMD  [TP20_SMD]
TP37  TP20_SMD  [TP20_SMD]
U26  TLC59282DBQR  [QSOP24_25_340X150_1-8]
sheet 12.HARDWARE SCHEMATIC
ACC2  PLAIN WASHER_M3  [NA]
ACC3  PLAIN WASHER_M3  [NA]
ACC4  PLAIN WASHER_M3  [NA]
ACC5  PLAIN WASHER_M3  [NA]
ACC6  PLAIN WASHER_M3  [NA]
ACC7  PLAIN WASHER_M3  [NA]
ACC8  PLAIN WASHER_M3  [NA]
ACC9  PLAIN WASHER_M3  [NA]
ACC10  PLAIN WASHER_M3  [NA]
ACC11  PLAIN WASHER_M3  [NA]
ACC12  PLAIN WASHER_M3  [NA]
ACC13  PLAIN WASHER_M3  [NA]
ACC14  MCH067  [NA]
ACC15  PLAIN WASHER_M3  [NA]
ACC16  PLAIN WASHER_M3  [NA]
ACC17  PLAIN WASHER_M3  [NA]
ACC18  PLAIN WASHER_M3  [NA]
ACC19  PLAIN WASHER_M3  [NA]
ACC20  PLAIN WASHER_M3  [NA]
ACC21  PLAIN WASHER_M3  [NA]
ACC22  PLAIN WASHER_M3  [NA]
ACC23  PLAIN WASHER_M3  [NA]
ACC24  PLAIN WASHER_M3  [NA]
FID1  FID_40X80  [FID_40X80]
FID2  FID_40X80  [FID_40X80]
FID3  FID_40X80  [FID_40X80]
LBL1  THT-103-423-10  [NA]
LBL2  THT-103-423-10  [NA]
LBL3  THT-103-423-10  [NA]
Logo1  Texas Intruments  [TI_Stacked_Overlay_Small]
Logo2  For Evaluation only; not FCC approved for resale  [FCC_disclaimer]
Logo3  WEEE Mark  [TI_Stacked_Overlay_Small]
Logo4  CE Mark  [TI_Stacked_Overlay_Small]
M1  728  [NA]
M2  728  [NA]
M3  728  [NA]
M4  728  [NA]
MH1  PAN HEAD_M2.5 X 12  [NA]
MH2  PAN HEAD_M2.5 X 12  [NA]
MH3  PAN HEAD_M2.5 X 12  [NA]
MH4  PAN HEAD_M2.5 X 12  [NA]
MH5  PAN HEAD_M2.5 X 4  [NA]
MH6  PAN HEAD_M2.5 X 4  [NA]
MH7  PAN HEAD_M2.5 X 4  [NA]
MH8  PAN HEAD_M2.5 X 4  [NA]
MH9  HEX SPACER_M2.5 X 6  [NA]
MH10  HEX SPACER_M2.5 X 6  [NA]
MH11  HEX SPACER_M2.5 X 6  [NA]
MH12  HEX SPACER_M2.5 X 6  [NA]
MH13  HEX SPACER_M2.5 X 6  [NA]
MH14  HEX SPACER_M2.5 X 9  [NA]
MH15  HEX SPACER_M2.5 X 9  [NA]
MH16  HEX SPACER_M2.5 X 40  [NA]
MH17  HEX SPACER_M2.5 X 40  [NA]
MH18  HEX SPACER_M2.5 X 40  [NA]
MH19  HEX SPACER_M2.5 X 40  [NA]
MH20  PAN HEAD_M2.5 X 4  [NA]
MH21  PAN HEAD_M2.5 X 4  [NA]
MH22  PAN HEAD_M2.5 X 4  [NA]
MH23  PAN HEAD_M2.5 X 4  [NA]
MH24  PAN HEAD_M2.5 X 4  [NA]
MH25  PAN HEAD_M2.5 X 4  [NA]
MH26  PAN HEAD_M2.5 X 4  [NA]
MH27  PAN HEAD_M2.5 X 4  [NA]
MH28  HEX NUT_M2.5  [NA]
MH29  HEX NUT_M2.5  [NA]
MH30  HEX NUT_M2.5  [NA]
MH31  HEX NUT_M2.5  [NA]
MH32  HEX NUT_M2.5  [NA]
MH33  HEX NUT_M2.5  [NA]
MH35  HEX SPACER_M2.5 X 9  [NA]
MH36  HEX NUT_M2.5  [NA]
PCB1  PROC102

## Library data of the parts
C1 = CAP: CAP CERAMIC 0.1uF 25V 20% X5R 0402; Chkd/date: MANIRAJA/170820; Crtd /date: ALVY/170820; Custom_Duty: 15%; Customs_HS_Code: 85322990; Distributor_name: DIGIKEY; Distributor_part_number: 732-7495-1-ND; Footprint Path: Y:\MIS_DATABASE\Library\ALTIUM_TOOL\PCB_FOOTPRINTS\Altium_Footprint_Lib.PcbLib; Height: 0.55MM; Library Path: Y:\MIS_DATABASE\Library\ALTIUM_TOOL\SCHEMATICS_PARTS\MS_DISCRETE_Library.schlib; Mfr_name: WURTH ELECTRONICS; Mfr_part_number: 885012105018; Mistral Part No: 120020080003-R; Package: 0402; Part_type: CAPACITORS\CERAMIC; Project: AM64x_EVM_BRD; RoHS: RoHS; Temperature: -55°C+85°C; Tolerance: 20%; Voltage: 25V; Wattage: NA; Weight: 0.65mg; Datasheet: Y:\MIS_DATABASE\DATASHEETS\CAPACITORS\885012105018.PDF
C2 C4 C6 = CAP: CAP CERAMIC 1uF 10V 20% X5R 0402; Chkd/date: MANIRAJA/210820; Crtd /date: ALVY/190820; Custom_Duty: 15%; Customs_HS_Code: 85322990; Distributor_name: DIGIKEY; Distributor_part_number: 732-7489-1-ND; Footprint Path: Y:\MIS_DATABASE\Library\ALTIUM_TOOL\PCB_FOOTPRINTS\Altium_Footprint_Lib.PcbLib; Height: 0.55MM; Library Path: Y:\MIS_DATABASE\Library\ALTIUM_TOOL\SCHEMATICS_PARTS\MS_DISCRETE_Library.schlib; Mfr_name: WURTH ELECTRONICS; Mfr_part_number: 885012105012; Mistral Part No: 120020080009-R; Package: 0402; Part_type: CAPACITORS\CERAMIC; Project: AM64x_EVM_BRD; RoHS: RoHS; Temperature: -55°C+85°C; Tolerance: 20%; Voltage: 10V; Wattage: NA; Weight: 0.65mg; Datasheet: Y:\MIS_DATABASE\DATASHEETS\CAPACITORS\885012105012.PDF
C3 C5 C7-C10 C15-C17 C20-C22 C25-C27 C30-C35 C44-C46 C63 = CAP: CAP CERAMIC 0.1uF 25V 20% X5R 0402; Alt_Mfr_name: YAGEO AMERICA; Alt_Mfr_part_number: CC0402KRX5R8BB104; Chkd/date: MANIRAJA/170820; Crtd /date: ALVY/170820; Custom_Duty: 15%; Customs_HS_Code: 85322990; Distributor_name: DIGIKEY; Distributor_part_number: 732-7495-1-ND; Footprint Path: Y:\MIS_DATABASE\Library\ALTIUM_TOOL\PCB_FOOTPRINTS\Altium_Footprint_Lib.PcbLib; Height: 0.55MM; Library Path: Y:\MIS_DATABASE\Library\ALTIUM_TOOL\SCHEMATICS_PARTS\MS_DISCRETE_Library.schlib; Mfr_name: WURTH ELECTRONICS; Mfr_part_number: 885012105018; Mistral Part No: 120020080003-R; Package: 0402; Part_type: CAPACITORS\CERAMIC; Project: AM64x_EVM_BRD; RoHS: RoHS; Temperature: -55°C+85°C; Tolerance: 20%; Voltage: 25V; Wattage: NA; Weight: 0.65mg; Datasheet: Y:\MIS_DATABASE\DATASHEETS\CAPACITORS\885012105018.PDF
J1 = CON_XMC30X5_M_SEAM: CON XMC 5X30 1.27MM PITCH MALE ST SMD; Chkd/date: MANIRAJA/080720; Crtd /date: ALVY/080720; Custom_Duty: 24%; Customs_HS_Code: 85369090; Distributor_name: DIGIKEY; Distributor_part_number: SEAM-30-03.5-L-05-2-A-K-TR-ND; Footprint Path: Y:\MIS_DATABASE\Library\ALTIUM_TOOL\PCB_FOOTPRINTS\Altium_Footprint_Lib.PcbLib; Height: 7.41MM; Library Path: Y:\MIS_DATABASE\Library\ALTIUM_TOOL\SCHEMATICS_PARTS\MS_CONNECTOR_Library.schlib; Mfr_name: SAMTEC; Mfr_part_number: SEAM-30-03.5-L-05-2-A-K-TR; Mistral Part No: 150020070006-R; Package: SMD; Part_type: CONNECTOR\XMC; Project: AM64x-GP_EVM BRD; RoHS: RoHS; Temperature: -55°C+125°C; Tolerance: NA; Voltage: NA; Wattage: NA; Weight: NA; Datasheet: Y:\MIS_DATABASE\DATASHEETS\CONNECTORS\SEAM-SER.PDF
R1 = RESISTOR: RES 0E 1/16W JUMPER 0402; Chkd/date: VASANTHA/201216; Crtd /date: MUDDU/190810; Custom_Duty: 15%; Customs_HS_Code: 85332119; Distributor_name: DIGIKEY; Distributor_part_number: 541-0.0JCT-ND; Footprint Path: Y:\MIS_DATABASE\Library\ALTIUM_TOOL\PCB_FOOTPRINTS\Altium_Footprint_Lib.PcbLib; Height: 0.40MM; Library Path: Y:\MIS_DATABASE\Library\ALTIUM_TOOL\SCHEMATICS_PARTS\MS_DISCRETE_Library.schlib; Mfr_name: VISHAY; Mfr_part_number: CRCW04020000Z0ED; Mistral Part No: 110010080019-R; Package: 0402; Part_type: RESISTORS\FIXED; Project: PB_BUGBASE; RoHS: RoHS; Temperature: -55°C+155°C; Tolerance: NA; Voltage: NA; Wattage: 1/16W; Weight: 0.65mg; Datasheet: Y:\MIS_DATABASE\DATASHEETS\RESISTORS\CRCW0603.PDF
R2-R8 R69-R73 = RESISTOR: RES 10K 1/16W 5% 0402; Chkd/date: VASANTHA/061216; Crtd /date: MAZHAR/230805; Custom_Duty: 15%; Customs_HS_Code: 85332119; Distributor_name: DIGIKEY; Distributor_part_number: 311-10KJRCT-ND; Footprint Path: Y:\MIS_DATABASE\Library\ALTIUM_TOOL\PCB_FOOTPRINTS\Altium_Footprint_Lib.PcbLib; Height: 0.40MM; Library Path: Y:\MIS_DATABASE\Library\ALTIUM_TOOL\SCHEMATICS_PARTS\MS_DISCRETE_Library.schlib; Mfr_name: YAGEO AMERICA; Mfr_part_number: RC0402JR-0710KL; Mistral Part No: 110011060021-R; Package: 0402; Part_type: RESISTORS\FIXED; Project: HSE; RoHS: RoHS; Temperature: -55°C+155°C; Tolerance: 5%; Voltage: NA; Wattage: 1/16W; Weight: 0.65mg; Datasheet: Y:\MIS_DATABASE\DATASHEETS\RESISTORS\RCXXXXL-SER_MAR18.PDF
U1 = CAT24C256WI-GT3_SOIC8: IC 256K I2C CMOS SERIAL EEPROM SOIC8; Chkd/date: MANIRAJA/130617; Crtd /date: MUDDU/270510; Custom_Duty: 15%; Customs_HS_Code: 85423100; Distributor_name: DIGIKEY; Distributor_part_number: CAT24C256WI-GT3-ND; Height: 1.75MM; Mfr_name: ON SEMICONDUCTOR; Mistral Part No: 141110050004-R; Package: SOIC8; Part_type: ICS\DIGITAL\MEMORY; Project: CENTAURUS; RoHS: RoHS; Temperature: -40°C+85°C; Tolerance: NA; Voltage: NA; Wattage: NA; Weight: 540mg; Datasheet: Y:\MIS_DATABASE\DATASHEETS\ICS\MEMORY\CAT24C256WI.PDF
J2-J9 = HEADER_10X2: CON HDR 2X10 2.54MM PITCH ST TH; Chkd/date: NAVEED/140515; Crtd /date: MAZHAR/020909; Custom_Duty: 0.24; Customs_HS_Code: 85369090; Distributor_name: DIGIKEY; Distributor_part_number: SAM1032-10-ND; Height: 5.02MM; Mfr_name: SAMTEC; Mfr_part_number: TSW-110-07-S-D; Mistral Part No: 150009090001-R; Package: THRU-HOLE; Part_type: CONNECTOR\HEADERS; Project: SMART VIEW_NVR; RoHS: RoHS; Temperature: NA; Tolerance: NA; Voltage: NA; Wattage: NA; Weight: NA; Datasheet: Y:\MIS_DATABASE\DATASHEETS\CONNECTORS\TSW-106-23-T-S.PDF
U2 U4 U7 U9 U11 U12 U17 = TS3L301_TSSOP48: IC 16-8BIT SPDT GIGABIT LAN SWITCH WITH LOW AND FLAT ON-STATE RESISTANCE TSSOP48; Chkd/date: MANIRAJA/220720; Crtd /date: ALVY/210720; Custom_Duty: 15%; Customs_HS_Code: 85423100; Distributor_name: DIGIKEY; Distributor_part_number: 296-17533-1-ND; Footprint Path: Y:\MIS_DATABASE\Library\ALTIUM_TOOL\PCB_FOOTPRINTS\Altium_Footprint_Lib.PcbLib; Height: 1.20MM; Library Path: Y:\MIS_DATABASE\Library\ALTIUM_TOOL\SCHEMATICS_PARTS\MS_ANALOG-APPLICATION_Library.schlib; Mfr_name: TEXAS INSTRUMENTS; Mistral Part No: 140120070002-R; Package: TSSOP48; Part_type: ICS\ANALOG\SWITCH; Project: AM64x-GP_EVM BRD; RoHS: RoHS; Temperature: -40°C+85°C; Tolerance: NA; Voltage: NA; Wattage: NA; Weight: 223.2mg; Datasheet: Y:\MIS_DATABASE\DATASHEETS\MISC\SWITCHES\TS3L301.PDF
J18 = HEADER_3X2: CON HDR 2X3 2.54MM PITCH ST TH; Chkd/date: MANIRAJA/230118; Crtd /date: MANIRAJA/220118; Custom_Duty: 24%; Customs_HS_Code: 85369090; Distributor_name: DIGIKEY; Distributor_part_number: SAM1034-03-ND; Height: 8.38MM; Mfr_name: SAMTEC; Mfr_part_number: TSW-103-07-T-D; Mistral Part No: 150018010019-R; Package: THRU-HOLE; Part_type: CONNECTOR\HEADERS; Project: TI_MAXIE_CPB; RoHS: RoHS; Temperature: -55°C+105°C; Tolerance: NA; Voltage: NA; Wattage: NA; Weight: NA; Datasheet: Y:\MIS_DATABASE\DATASHEETS\CONNECTORS\TSW-MK.PDF
TP1-TP6 TP31-TP37 = TESTPOINT: TESTPOINT CIR 20 SMD; Chkd/date: SHREESHAIL/171006; Crtd /date: MAZHAR/171006; Custom_Duty: NA; Customs_HS_Code: NA; Distributor_name: NA; Distributor_part_number: NA; Footprint Path: Y:\MIS_DATABASE\Library\ALTIUM_TOOL\PCB_FOOTPRINTS\Altium_Footprint_Lib.PcbLib; Height: NA; Library Path: Y:\MIS_DATABASE\Library\ALTIUM_TOOL\SCHEMATICS_PARTS\MS_DISCRETE_Library.schlib; MECHANICAL 3D STEP FILE: NA; Mfr_name: LOCAL; Mistral Part No: NA; Package: SMD; Project: BT MODULE_CSRBC04; RoHS: NA; Temperature: NA; Tolerance: NA; Voltage: NA; Wattage: NA; Weight: NA; Datasheet: NA
ACC1 = ACCESSORY: ACCESSORIE JUMPER SHORTING GOLD FLASH; Chkd/date: SUHAS\211010; Crtd /date: USMAN/301208; Distributor_name: DIGIKEY; Distributor_part_number: S9001-ND; Footprint Path: Y:\MIS_DATABASE\Library\ALTIUM_TOOL\PCB_FOOTPRINTS\Altium_Footprint_Lib.PcbLib; Library Path: Y:\MIS_DATABASE\Library\ALTIUM_TOOL\SCHEMATICS_PARTS\MS_MECHANICAL_Library.schlib; Mfr_name: SULLINS CONNECTOR; Mistral Part No: 160009030153-R; Part_type: ACCESSORIES; Project: SMART VIEW_NVR; RoHS: RoHS; Temperature: -55°C+105°C; Datasheet: Y:\MIS_DATABASE\DATASHEETS\MISC\MODULES\SPC02SYAN.PDF
J11 = HEADER_3X1: HDR 1X3 2.54MM PITCH ST TH; Chkd/date: VASANTHA/290616; Crtd /date: VASANTHA/290616; Custom_Duty: 15%; Customs_HS_Code: 85322990; Distributor_name: DIGIKEY; Distributor_part_number: 609-3471-ND; Height: 8.58MM; Mfr_name: FCI; Mfr_part_number: 68001-403HLF; Mistral Part No: 150016060025-R; Package: THRU-HOLE; Part_type: CONNECTOR\HEADERS; Project: IKEYP; RoHS: RoHS; Temperature: -40°C+105°C; Tolerance: NA; Voltage: NA; Wattage: NA; Weight: NA; Datasheet: Y:\MIS_DATABASE\DATASHEETS\CONNECTORS\68000.PDF
LD1-LD5 LD7 LD9 LD11 LD13 LD15 LD17 LD19 LD21 = DIODE_LED: DIODE LED BRIGHT GREEN SMD; Chkd/date: MANIRAJA/220720; Crtd /date: ALVY/210720; Custom_Duty: 24%; Customs_HS_Code: 85439000; Distributor_name: DIGIKEY; Distributor_part_number: 732-4980-1-ND; Footprint Path: Y:\MIS_DATABASE\Library\ALTIUM_TOOL\PCB_FOOTPRINTS\Altium_Footprint_Lib.PcbLib; Height: 0.80MM; Library Path: Y:\MIS_DATABASE\Library\ALTIUM_TOOL\SCHEMATICS_PARTS\MS_OPTO_Library.schlib; Mfr_name: WURTH ELECTRONICS; Mistral Part No: 130020070019-R; Package: SMD; Part_type: OPTO\LED; Project: AM64x-IO LINK BRD; RoHS: RoHS; Temperature: -40°C+85°C; Tolerance: NA; Voltage: NA; Wattage: NA; Weight: 25mg; Datasheet: Y:\MIS_DATABASE\DATASHEETS\DISCRETES\LEDS\150060VS75000.PDF
LD6 LD8 LD10 LD12 LD14 LD16 LD18 LD20 = DIODE_LED: DIODE LED RED SMD; Chkd/date: MANIRAJA/180820; Crtd /date: ALVY/180820; Custom_Duty: 24%; Customs_HS_Code: 85439000; Distributor_name: DIGIKEY; Distributor_part_number: 732-12015-1-ND; Footprint Path: Y:\MIS_DATABASE\Library\ALTIUM_TOOL\PCB_FOOTPRINTS\Altium_Footprint_Lib.PcbLib; Height: 0.50MM; Library Path: Y:\MIS_DATABASE\Library\ALTIUM_TOOL\SCHEMATICS_PARTS\MS_OPTO_Library.schlib; Mfr_name: WURTH ELECTRONICS; Mistral Part No: 130020080014-R; Package: SMD; Part_type: OPTO\LED; Project: AM64x_EVM_BRD; RoHS: RoHS; Temperature: -40°C+85°C; Tolerance: NA; Voltage: NA; Wattage: NA; Weight: 29mg; Datasheet: Y:\MIS_DATABASE\DATASHEETS\DISCRETES\LEDS\150060RS55040.PDF
Q1-Q3 = MOSFET_BSS138W: IC MOSFET N-CHANNEL 50V 200mA SOT23-3; Chkd/date: MANIRAJA/250219; Crtd /date: JEBRAN/060416; Custom_Duty: 15%; Customs_HS_Code: 85423100; Distributor_name: DIGIKEY; Distributor_part_number: BSS138LT1GOSCT-ND; Footprint Path: Y:\MIS_DATABASE\Library\ALTIUM_TOOL\PCB_FOOTPRINTS\Altium_Footprint_Lib.PcbLib; Height: 1.11MM; Library Path: Y:\MIS_DATABASE\Library\ALTIUM_TOOL\SCHEMATICS_PARTS\MS_MOSFET_Library.schlib; Mfr_name: ON SEMICONDUCTOR; Mistral Part No: 142016040001-R; Package: SOT23-3; Part_type: ICS\POWER\MOSFET; Project: LRDE_ABCM; RoHS: RoHS; Temperature: -55°C+150°C; Tolerance: NA; Voltage: NA; Wattage: NA; Weight: 8mg; Datasheet: Y:\MIS_DATABASE\DATASHEETS\DISCRETES\TRANSISTORS_FETS\BSS138LT1G.PDF
R64-R68 = RESISTOR: RES 220E 1/16W 5% 0402; Chkd/date: VASANTHA/291216; Crtd /date: GEETHA/260406; Custom_Duty: 15%; Customs_HS_Code: 85332119; Distributor_name: DIGIKEY; Distributor_part_number: P220JCT-ND; Footprint Path: Y:\MIS_DATABASE\Library\ALTIUM_TOOL\PCB_FOOTPRINTS\Altium_Footprint_Lib.PcbLib; Height: 0.40MM; Library Path: Y:\MIS_DATABASE\Library\ALTIUM_TOOL\SCHEMATICS_PARTS\MS_DISCRETE_Library.schlib; Mfr_name: PANASONIC-ECG; Mfr_part_number: ERJ-2GEJ221X; Mistral Part No: 110009030506-R; Package: 0402; Part_type: RESISTORS\FIXED; Project: RED EYE; RoHS: RoHS; Temperature: -55°C+155°C; Tolerance: 5%; Voltage: NA; Wattage: 1/16W; Weight: 0.8g/1000pcs; Datasheet: Y:\MIS_DATABASE\DATASHEETS\RESISTORS\ERJ12.PDF
U26 = TLC59282_SSOP24: IC 16-CH CONSTANT-CURRENT LED DRIVER WITH 4-CH GROUPED DELAY SSOP24; Chkd/date: MANIRAJA/210720; Crtd /date: ALVY/170720; Custom_Duty: 15%; Customs_HS_Code: 85423100; Distributor_name: DIGIKEY; Distributor_part_number: 296-28098-1-ND; Footprint Path: Y:\MIS_DATABASE\Library\ALTIUM_TOOL\PCB_FOOTPRINTS\Altium_Footprint_Lib.PcbLib; Height: 1.75MM; Library Path: Y:\MIS_DATABASE\Library\ALTIUM_TOOL\SCHEMATICS_PARTS\MS_MISCINTERFACE_Library.schlib; Mfr_name: TEXAS INSTRUMENTS; Mistral Part No: 141020070001-R; Package: SSOP24; Part_type: ICS\INTERFACE\DISPLAY DRIVER; Project: AM64x-GP_EVM BRD; RoHS: RoHS; Temperature: -40°C+85°C; Tolerance: NA; Voltage: NA; Wattage: NA; Weight: 1700mg; Datasheet: Y:\MIS_DATABASE\DATASHEETS\ICS\INTERFACE\TLC59282.PDF
ACC2-ACC13 ACC15-ACC24 = WASHER_PLAIN: PLAIN WASHER FOR M3 SS-316; Chkd/date: MANIRAJA/190218; Crtd /date: MANIRAJA/190218; Distributor_name: DIGIKEY; Distributor_part_number: 36-4692-ND; Footprint Path: Y:\MIS_DATABASE\Library\ALTIUM_TOOL\PCB_FOOTPRINTS\Altium_Footprint_Lib.PcbLib; Library Path: Y:\MIS_DATABASE\Library\ALTIUM_TOOL\SCHEMATICS_PARTS\MS_MECHANICAL_Library.schlib; Mfr_name: KEYSTONE; Mfr_part_number: 4692; Mistral Part No: 160018020078-R; Package: SS; Part_type: MECHANICAL\WASHERS; Project: TI_MAXIE_CPB; RoHS: RoHS; Datasheet: Y:\MIS_DATABASE\DATASHEETS\MISC\MECHANICAL\4692.PDF
ACC14 = ACCESSORY: ACCESSORIE IO LINK CONNECTOR SUPPORT PLATE; Chkd/date: MANIRAJA/221020; Crtd /date: MANIRAJA/221020; Mfr_name: MISTRAL; Mfr_part_number: 160020100060; Mistral Part No: 160020100060; Part_type: MECHANICAL; Project: AM64X
FID1-FID3 = Fiducial
LBL1-LBL3 = ACCESSORY_THT-3-423-10: ACCESSORIE 1 WORKHORSE POLYSTER LABLE 0.25" X 1"; Chkd/date: MANIRAJA/270218; Crtd /date: ALVY/260218; Footprint Path: Y:\MIS_DATABASE\Library\ALTIUM_TOOL\PCB_FOOTPRINTS\Altium_Footprint_Lib.PcbLib; Library Path: Y:\MIS_DATABASE\Library\ALTIUM_TOOL\SCHEMATICS_PARTS\MS_MECHANICAL_Library.schlib; Mfr_name: BRADY; Mistral Part No: 160018020185; Part_type: ACCESSORIES; Project: TI_MAXIE_CPB
Logo1 Logo3 Logo4 = TI_Logo
Logo2 = FCC_disclaimer
M1-M4 = ACCESSORY: ACCESSORIE RECESSED BUMPER 19.05MM DIA; Chkd/date: MANIRAJA/110718; Crtd /date: MANIRAJA/110718; Distributor_name: DIGIKEY; Distributor_part_number: 36-728-ND; Mfr_name: KEYSTONE; Mistral Part No: 160018070042-R; Part_type: ACCESSORIES; Project: TI_MAXIE_CPB; RoHS: RoHS; Weight: 2042mg; Datasheet: Y:\MIS_DATABASE\DATASHEETS\MISC\ACCESSORIES\728.PDF
MH1-MH4 = SCREW_PAN: PHILLIPS PAN HEAD SCREW - M2.5 X 12; Chkd/date: MANIRAJA/110718; Crtd /date: MANIRAJA/110718; Distributor_name: DIGIKEY; Distributor_part_number: 36-29304-ND; Height: 12.00MM; Mfr_name: KEYSTONE; Mfr_part_number: 29304; Mistral Part No: 160018070043-R; Part_type: ACCESSORIES; Project: TI_MAXIE_CPB; RoHS: RoHS; Datasheet: Y:\MIS_DATABASE\DATASHEETS\MISC\MECHANICAL\29304.PDF
MH5-MH8 MH20-MH27 = SCREW_PAN: PHILLIPS PAN HEAD SCREW - M2.5 X 4 SS-316; Chkd/date: MANIRAJA/190218; Crtd /date: MANIRAJA/190218; Distributor_name: DIGIKEY; Distributor_part_number: 36-29300-ND; Footprint Path: Y:\MIS_DATABASE\Library\ALTIUM_TOOL\PCB_FOOTPRINTS\Altium_Footprint_Lib.PcbLib; Height: 4.00MM; Library Path: Y:\MIS_DATABASE\Library\ALTIUM_TOOL\SCHEMATICS_PARTS\MS_MECHANICAL_Library.schlib; Mfr_name: KEYSTONE; Mfr_part_number: 29300; Mistral Part No: 160018020076-R; Package: SS; Part_type: MECHANICAL\SCREWS; Project: TI_MAXIE_CPB; RoHS: RoHS; Datasheet: Y:\MIS_DATABASE\DATASHEETS\MISC\MECHANICAL\29300.PDF
MH9-MH13 = HEX_SPACER_FF: HEX SPACER FEMALE TO FEMALE M2.5 X 6MM ALUMINIUM; Chkd/date: MANIRAJA/220921; Crtd /date: ALVY/220921; Distributor_name: DIGIKEY; Distributor_part_number: 1772-1108-ND; Height: 6.00MM; Mfr_name: RAF; Mfr_part_number: M1253-2545-AL; Mistral Part No: 160021090008-R; Package: ALUMINIUM; Part_type: MECHANICAL\SPACER; Project: TI_AM62x SKEVM_BRD; RoHS: RoHS; Weight: 227mg; Datasheet: Y:\MIS_DATABASE\DATASHEETS\MISC\MECHANICAL\M1253-2545-AL.PDF
MH14 MH15 MH35 = HEX_SPACER_MF: HEX SPACER MALE TO FEMALE M2.5 X 9MM STEEL; Chkd/date: MANIRAJA/220921; Crtd /date: ALVY/220921; Distributor_name: DIGIKEY; Distributor_part_number: 1772-1637-ND; Height: 9.00MM; Mfr_name: RAF; Mfr_part_number: M2104-2545-SS; Mistral Part No: 160021090009-R; Package: STEEL; Part_type: MECHANICAL\SPACER; Project: TI_AM62x SKEVM_BRD; RoHS: RoHS; Weight: 1177mg; Datasheet: Y:\MIS_DATABASE\DATASHEETS\MISC\MECHANICAL\M2104-2545-SS.PDF
MH16-MH19 = HEX_SPACER_MF: HEX SPACER MALE TO FEMALE M2.5 X 40MM STEEL; Chkd/date: MANIRAJA/061020; Crtd /date: ALVY/061020; Distributor_name: DIGIKEY; Distributor_part_number: 1772-4191-ND; Height: 40.00MM; Mfr_name: RAF; Mfr_part_number: M2125-2545-SS; Mistral Part No: 160020100011-R; Package: STEEL; Part_type: MECHANICAL\SPACER; Project: AM64X_3AXIS_ADAPTER_INTERFACE CARD; RoHS: RoHS; Datasheet: Y:\MIS_DATABASE\DATASHEETS\MISC\MECHANICAL\M2125-2545-SS.PDF
MH28-MH33 MH36 = NUT_HEX: M2.5 NUT HEX STEEL; Chkd/date: MANIRAJA/200318; Crtd /date: MANIRAJA/200318; Distributor_name: DIGIKEY; Distributor_part_number: 36-4707-ND; Footprint Path: Y:\MIS_DATABASE\Library\ALTIUM_TOOL\PCB_FOOTPRINTS\Altium_Footprint_Lib.PcbLib; Library Path: Y:\MIS_DATABASE\Library\ALTIUM_TOOL\SCHEMATICS_PARTS\MS_MECHANICAL_Library.schlib; Library Ref: HEX_NUT; Mfr_name: KEYSTONE; Mfr_part_number: 4707; Mistral Part No: 160018030007-R; Package: SS; Part_type: MECHANICAL\NUT; Project: TI_SVB_MAXWELL_LCD-AB; RoHS: RoHS; Datasheet: Y:\MIS_DATABASE\DATASHEETS\MISC\MECHANICAL\4707.PDF
PCB1 = PCB: IO-Link Board Bare PCB; Mistral Part No: FY20-21/00416000401

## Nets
DGND: C1.1 C2.2 C3.2 C4.2 C5.2 C6.2 C7.2 C8.2 C9.2 C10.2 C15.2 C16.2 C17.2 C20.2 C21.2 C22.2 C25.2 C26.2 C27.2 C30.2 C31.2 C32.2 C33.2 C34.2 C35.2 C44.2 C45.2 C46.2 C63.2 J1.A6 J1.A10 J1.A16 J1.A18 J1.A23 J1.A24 J1.A25 J1.B3 J1.B5 J1.B6 J1.B10 J1.B16 J1.B18 J1.B19 J1.B23 J1.B25 J1.B26 J1.B27 J1.B28 J1.B30 J1.C4 J1.C7 J1.C10 J1.C13 J1.C16 J1.C17 J1.C18 J1.C19 J1.C20 J1.C25 J1.C30 J1.D4 J1.D7 J1.D10 J1.D13 J1.D16 J1.D20 J1.D25 J1.D30 J1.E5 J1.E6 J1.E7 J1.E10 J1.E16 J1.E20 J1.E22 J1.E25 J1.E28 J1.E29 J2.2 J2.4 J2.6 J2.8 J2.10 J2.12 J2.14 J2.16 J2.18 J2.20 J3.2 J3.4 J3.6 J3.8 J3.10 J3.12 J3.14 J3.16 J3.18 J3.20 J4.2 J4.4 J4.6 J4.8 J4.10 J4.12 J4.14 J4.16 J4.18 J4.20 J5.2 J5.4 J5.6 J5.8 J5.10 J5.12 J5.14 J5.16 J5.18 J5.20 J6.2 J6.4 J6.6 J6.8 J6.10 J6.12 J6.14 J6.16 J6.18 J6.20 J7.2 J7.4 J7.6 J7.8 J7.10 J7.12 J7.14 J7.16 J7.18 J7.20 J8.2 J8.4 J8.6 J8.8 J8.10 J8.12 J8.14 J8.16 J8.18 J8.20 J9.2 J9.4 J9.6 J9.8 J9.10 J9.12 J9.14 J9.16 J9.18 J9.20 J11.3 J18.5 LD3.1(CATHODE) LD4.1(CATHODE) Q1.2(S) Q2.2(S) Q3.2(S) R1.1 R6.2 R7.2 R8.2 R69.2 R70.2 R73.2 TP4.1(TP) TP5.1(TP) TP6.1(TP) TP36.1(TP) U1.4(VSS) U2.3(GND) U2.5(GND) U2.7(GND) U2.9(GND) U2.11(GND) U2.13(GND) U2.16(GND) U2.18(GND) U2.20(GND) U2.22(GND) U2.27(GND) U2.30(GND) U2.33(GND) U2.37(GND) U2.40(GND) U2.43(GND) U2.46(GND) U4.3(GND) U4.5(GND) U4.7(GND) U4.9(GND) U4.11(GND) U4.13(GND) U4.16(GND) U4.18(GND) U4.20(GND) U4.22(GND) U4.27(GND) U4.30(GND) U4.33(GND) U4.37(GND) U4.40(GND) U4.43(GND) U4.46(GND) U7.3(GND) U7.5(GND) U7.7(GND) U7.9(GND) U7.11(GND) U7.13(GND) U7.16(GND) U7.18(GND) U7.20(GND) U7.22(GND) U7.27(GND) U7.30(GND) U7.33(GND) U7.37(GND) U7.40(GND) U7.43(GND) U7.46(GND) U9.3(GND) U9.5(GND) U9.7(GND) U9.9(GND) U9.11(GND) U9.13(GND) U9.16(GND) U9.18(GND) U9.20(GND) U9.22(GND) U9.27(GND) U9.30(GND) U9.33(GND) U9.37(GND) U9.40(GND) U9.43(GND) U9.46(GND) U11.3(GND) U11.5(GND) U11.7(GND) U11.9(GND) U11.11(GND) U11.13(GND) U11.16(GND) U11.18(GND) U11.20(GND) U11.22(GND) U11.27(GND) U11.30(GND) U11.33(GND) U11.37(GND) U11.40(GND) U11.43(GND) U11.46(GND) U12.3(GND) U12.5(GND) U12.7(GND) U12.9(GND) U12.11(GND) U12.13(GND) U12.16(GND) U12.18(GND) U12.20(GND) U12.22(GND) U12.27(GND) U12.30(GND) U12.33(GND) U12.37(GND) U12.40(GND) U12.43(GND) U12.46(GND) U17.3(GND) U17.5(GND) U17.7(GND) U17.9(GND) U17.11(GND) U17.13(GND) U17.16(GND) U17.18(GND) U17.20(GND) U17.22(GND) U17.27(GND) U17.30(GND) U17.33(GND) U17.37(GND) U17.40(GND) U17.43(GND) U17.46(GND) U26.1(GND) U26.21(BLANK) ; also on sheet 9 10 11 12
VCC1V8_HSE: C2.1 C3.1 J1.C2 J1.C3 R71.1 TP3.1(TP) ; also on sheet 10
VCC3V3_IO_HSE: C1.2 C4.1 C5.1 C8.1 C9.1 C10.1 C15.1 C16.1 C17.1 C20.1 C21.1 C22.1 C25.1 C26.1 C27.1 C30.1 C31.1 C32.1 C33.1 C34.1 C35.1 C44.1 C45.1 C46.1 C63.1 J1.A27 J1.A28 J1.A29 J11.1 LD6.2(ANODE) LD7.2(ANODE) LD8.2(ANODE) LD9.2(ANODE) LD10.2(ANODE) LD11.2(ANODE) LD12.2(ANODE) LD13.2(ANODE) LD14.2(ANODE) LD15.2(ANODE) LD16.2(ANODE) LD17.2(ANODE) LD18.2(ANODE) LD19.2(ANODE) LD20.2(ANODE) LD21.2(ANODE) R2.1 R3.1 R4.1 R5.1 R64.1 R65.1 R67.1 R68.1 TP2.1(TP) U1.8(VCC) U2.1(VDD) U2.6(VDD) U2.12(VDD) U2.19(VDD) U2.36(VDD) U4.1(VDD) U4.6(VDD) U4.12(VDD) U4.19(VDD) U4.36(VDD) U7.1(VDD) U7.6(VDD) U7.12(VDD) U7.19(VDD) U7.36(VDD) U9.1(VDD) U9.6(VDD) U9.12(VDD) U9.19(VDD) U9.36(VDD) U11.1(VDD) U11.6(VDD) U11.12(VDD) U11.19(VDD) U11.36(VDD) U12.1(VDD) U12.6(VDD) U12.12(VDD) U12.19(VDD) U12.36(VDD) U17.1(VDD) U17.6(VDD) U17.12(VDD) U17.19(VDD) U17.36(VDD) U26.24(VCC) ; also on sheet 9 10 11 12
VCC_5V0_HSE: C6.1 C7.1 J1.A1 J1.A2 J1.A3 R66.1 TP1.1(TP) ; also on sheet 10
VCC_24V0: TP37.1(TP) ; also on sheet 9 10 11 12
EEPROM0_A0: R2.2 R6.1 U1.1(A0)
EEPROM0_A1: R3.2 R7.1 U1.2(A1)
EEPROM0_A2: R4.2 R8.1 U1.3(A2)
EEPROM0_WP: R5.2 U1.7(WP)
EN_L+1: U7.44(1B2) ; also on sheet 9
EN_L+2: U7.39(2B2) ; also on sheet 9
EN_L+3: U7.32(4B2) ; also on sheet 9
EN_L+4: U7.31(5B2) ; also on sheet 9
EN_L+5: U7.45(0B2) ; also on sheet 9
EN_L+6: U7.26(6B2) ; also on sheet 9
EN_L+7: U7.38(3B2) ; also on sheet 9
EN_L+8: U7.25(7B2) ; also on sheet 9
EN_PHY_1: U9.45(0B2) ; also on sheet 11
EN_PHY_2: U9.44(1B2) ; also on sheet 11
EN_PHY_3: U9.39(2B2) ; also on sheet 11
EN_PHY_4: U9.38(3B2) ; also on sheet 11
EN_PHY_5: U9.32(4B2) ; also on sheet 12
EN_PHY_6: U9.31(5B2) ; also on sheet 12
EN_PHY_7: U9.26(6B2) ; also on sheet 12
EN_PHY_8: U9.25(7B2) ; also on sheet 12
FAULT_1: U11.45(0B2) ; also on sheet 11
FAULT_2: U11.44(1B2) ; also on sheet 11
FAULT_3: U11.39(2B2) ; also on sheet 11
FAULT_4: U11.38(3B2) ; also on sheet 11
FAULT_5: U11.32(4B2) ; also on sheet 12
FAULT_6: U11.31(5B2) ; also on sheet 12
FAULT_7: U11.26(6B2) ; also on sheet 12
FAULT_8: U11.25(7B2) ; also on sheet 12
GPMC0_AD0: J1.E14 U11.2(A0)
GPMC0_AD0_HDR: J6.1 U11.48(0B1)
GPMC0_AD1: J1.D14 U11.4(A1)
GPMC0_AD1_HDR: J6.3 U11.47(1B1)
GPMC0_AD2: J1.C14 U11.8(A2)
GPMC0_AD2_HDR: J6.5 U11.42(2B1)
GPMC0_AD3: J1.E15 U11.10(A3)
GPMC0_AD3_HDR: J6.7 U11.41(3B1)
GPMC0_AD4: J1.D15 U11.15(A4)
GPMC0_AD4_HDR: J6.9 U11.35(4B1)
GPMC0_AD5: J1.C15 U11.17(A5)
GPMC0_AD5_HDR: J6.11 U11.34(5B1)
GPMC0_AD6: J1.E17 U11.21(A6)
GPMC0_AD6_HDR: J6.13 U11.29(6B1)
GPMC0_AD7: J1.D17 U11.23(A7)
GPMC0_AD7_HDR: J6.15 U11.28(7B1)
GPMC0_AD8: J1.A22 J6.17
GPMC0_AD9: J1.A21 J6.19
GPMC0_AD10: J1.B21 J7.1
GPMC0_AD11: J1.E21 J7.3
GPMC0_AD12: J1.C21 J7.5
GPMC0_AD13: J1.D21 J7.7
GPMC0_AD14: J1.B20 J7.9
GPMC0_AD15: J1.A19 J7.11
GPMC0_CSn1: J1.E19 J7.17
GPMC0_CSn2: J1.D18 J7.13
GPMC0_CSn3: J1.D19 J7.15
GPMC0_DIR: J1.E18 J7.19
H_FAULT: U12.26(6B2) ; also on sheet 9
H_SEH: U12.32(4B2) ; also on sheet 9
H_SEL: U12.31(5B2) ; also on sheet 9
HSE_DETECT: J1.E4 R1.2
HSE_GPIO0_31: J1.B22 U12.15(A4)
HSE_GPIO0_31_HDR: J8.1 U12.35(4B1)
HSE_GPIO0_32: J1.C22 U12.17(A5)
HSE_GPIO0_32_HDR: J8.3 U12.34(5B1)
HSE_GPIO0_33: J1.D22 U12.21(A6)
HSE_GPIO0_33_HDR: J8.5 U12.29(6B1)
HSE_GPIO0_34: J1.C23 U12.10(A3)
HSE_GPIO0_34_HDR: J8.7 U12.41(3B1)
HSE_GPIO0_35: J1.B24 U12.4(A1)
HSE_GPIO0_35_HDR: J8.9 U12.47(1B1)
HSE_GPIO0_36: J1.A20 U12.2(A0)
HSE_GPIO0_36_HDR: J8.11 U12.48(0B1)
HSE_GPIO0_37: J1.C24 U12.8(A2)
HSE_GPIO0_37_HDR: J8.13 U12.42(2B1)
HSE_GPIO0_38: J1.E26 J8.15
HSE_GPIO0_39: J1.C26 J8.17
HSE_GPIO0_41: J1.D26 J8.19
HSE_MCAN0_RX/UART4_TXD: J1.E24 J3.19
HSE_MCAN0_TX/UART4_RXD: J1.D24 J3.17
HSE_MCAN1_RX/I2C3_SDA: J1.C29 J3.15
HSE_MCAN1_TX/I2C3_SCL: J1.D29 J3.13
L_FAULT: U12.45(0B2) ; also on sheet 9
L_SEH: U12.38(3B2) ; also on sheet 9
L_SEL: U12.44(1B2) ; also on sheet 9
LATCH: U17.39(2B2) U26.4(LAT)
LED_G1: LD21.1(CATHODE) U26.20(OUT15)
LED_G2: LD19.1(CATHODE) U26.18(OUT13)
LED_G3: LD17.1(CATHODE) U26.16(OUT11)
LED_G4: LD15.1(CATHODE) U26.14(OUT9)
LED_G5: LD13.1(CATHODE) U26.12(OUT7)
LED_G6: LD11.1(CATHODE) U26.10(OUT5)
LED_G7: LD9.1(CATHODE) U26.8(OUT3)
LED_G8: LD7.1(CATHODE) U26.6(OUT1)
LED_R1: LD20.1(CATHODE) U26.19(OUT14)
LED_R2: LD18.1(CATHODE) U26.17(OUT12)
LED_R3: LD16.1(CATHODE) U26.15(OUT10)
LED_R4: LD14.1(CATHODE) U26.13(OUT8)
LED_R5: LD12.1(CATHODE) U26.11(OUT6)
LED_R6: LD10.1(CATHODE) U26.9(OUT4)
LED_R7: LD8.1(CATHODE) U26.7(OUT2)
LED_R8: LD6.1(CATHODE) U26.5(OUT0)
LOAD_PULSE_SE: U12.39(2B2) ; also on sheet 9
MCU_PORz: J1.E30 J18.6 TP33.1(TP)
MCU_RESETSTATz: J1.E3 J18.4 TP32.1(TP)
MCU_RESETz: J1.D3 J18.2 TP31.1(TP)
MUX_CONTROL_1: R72.1 U2.24(SEL) U4.24(SEL) U7.24(SEL) U9.24(SEL) U11.24(SEL) U12.24(SEL) U17.24(SEL)
PRG0_HSE_ETH1_CLK: J1.A17 J18.3 TP35.1(TP)
PRG0_HSE_ETH2_CLK: J1.B17 J18.1 TP34.1(TP)
PRG0_MDIO0_MDC: J1.A5 J5.19
PRG0_MDIO0_MDIO: J1.A4 J5.17
PRG0_PRU0GPO0: J1.B12 Q1.1(G) R69.1 U2.2(A0)
PRG0_PRU0GPO0_HDR: J2.1 U2.48(0B1)
PRG0_PRU0GPO1: J1.E8 U2.4(A1)
PRG0_PRU0GPO1_HDR: J2.3 U2.47(1B1)
PRG0_PRU0GPO2: J1.A8 U2.8(A2)
PRG0_PRU0GPO2_HDR: J2.5 U2.42(2B1)
PRG0_PRU0GPO3: J1.A9 U2.10(A3)
PRG0_PRU0GPO3_HDR: J2.7 U2.41(3B1)
PRG0_PRU0GPO4: J1.A13 U2.15(A4)
PRG0_PRU0GPO4_HDR: J2.9 U2.35(4B1)
PRG0_PRU0GPO5: J1.C6 U2.17(A5)
PRG0_PRU0GPO5_HDR: J2.11 U2.34(5B1)
PRG0_PRU0GPO6: J1.D8 U2.21(A6)
PRG0_PRU0GPO6_HDR: J2.13 U2.29(6B1)
PRG0_PRU0GPO7: J1.B7 U2.23(A7)
PRG0_PRU0GPO7_HDR: J2.15 U2.28(7B1)
PRG0_PRU0GPO8: J1.A7 U4.2(A0)
PRG0_PRU0GPO8_HDR: J2.17 U4.48(0B1)
PRG0_PRU0GPO11: J1.B14 U4.4(A1)
PRG0_PRU0GPO11_HDR: J2.19 U4.47(1B1)
PRG0_PRU0GPO12: J1.A14 U4.8(A2)
PRG0_PRU0GPO12_HDR: J3.1 U4.42(2B1)
PRG0_PRU0GPO13: J1.C5 U4.10(A3)
PRG0_PRU0GPO13_HDR: J3.3 U4.41(3B1)
PRG0_PRU0GPO14: J1.C9 U4.15(A4)
PRG0_PRU0GPO14_HDR: J3.5 U4.35(4B1)
PRG0_PRU0GPO15: J1.D12 U4.17(A5)
PRG0_PRU0GPO15_HDR: J3.7 U4.34(5B1)
PRG0_PRU0GPO16: J1.E9 U4.21(A6)
PRG0_PRU0GPO16_HDR: J3.9 U4.29(6B1)
PRG0_PRU0GPO17: J1.B8 U4.23(A7)
PRG0_PRU0GPO17_HDR: J3.11 U4.28(7B1)
PRG0_PRU0GPO18: J1.B9 U7.4(A1)
PRG0_PRU0GPO18_HDR: J4.1 U7.47(1B1)
PRG0_PRU0GPO19: J1.B11 U7.8(A2)
PRG0_PRU0GPO19_HDR: J4.3 U7.42(2B1)
PRG0_PRU1GPO0: J1.A12 Q2.1(G) R70.1 U7.15(A4)
PRG0_PRU1GPO0_HDR: J4.5 U7.35(4B1)
PRG0_PRU1GPO1: J1.A11 U7.17(A5)
PRG0_PRU1GPO1_HDR: J4.7 U7.34(5B1)
PRG0_PRU1GPO2: J1.D9 U7.2(A0)
PRG0_PRU1GPO2_HDR: J4.9 U7.48(0B1)
PRG0_PRU1GPO3: J1.C8 U7.21(A6)
PRG0_PRU1GPO3_HDR: J4.11 U7.29(6B1)
PRG0_PRU1GPO4: J1.B13 U7.10(A3)
PRG0_PRU1GPO4_HDR: J4.13 U7.41(3B1)
PRG0_PRU1GPO5: J1.D6 U7.23(A7)
PRG0_PRU1GPO5_HDR: J4.15 U7.28(7B1)
PRG0_PRU1GPO6: J1.E11 U9.2(A0)
PRG0_PRU1GPO6_HDR: J4.17 U9.48(0B1)
PRG0_PRU1GPO8: J1.B4 U9.4(A1)
PRG0_PRU1GPO8_HDR: J4.19 U9.47(1B1)
PRG0_PRU1GPO11: J1.D11 U9.8(A2)
PRG0_PRU1GPO11_HDR: J5.1 U9.42(2B1)
PRG0_PRU1GPO12: J1.B15 U9.10(A3)
PRG0_PRU1GPO12_HDR: J5.3 U9.41(3B1)
PRG0_PRU1GPO13: J1.D5 U9.15(A4)
PRG0_PRU1GPO13_HDR: J5.5 U9.35(4B1)
PRG0_PRU1GPO14: J1.E12 U9.17(A5)
PRG0_PRU1GPO14_HDR: J5.7 U9.34(5B1)
PRG0_PRU1GPO15: J1.C11 U9.21(A6)
PRG0_PRU1GPO15_HDR: J5.9 U9.29(6B1)
PRG0_PRU1GPO16: J1.A15 U9.23(A7)
PRG0_PRU1GPO16_HDR: J5.11 U9.28(7B1)
PRG1_PRU1GPO18: J1.E13 J5.13
PRG1_PRU1GPO19: J1.C12 J5.15
RX_1: U2.45(0B2) ; also on sheet 11
RX_2: U2.44(1B2) ; also on sheet 11
RX_3: U2.39(2B2) ; also on sheet 11
RX_4: U2.38(3B2) ; also on sheet 11
RX_5: U2.32(4B2) ; also on sheet 12
RX_6: U2.31(5B2) ; also on sheet 12
RX_7: U2.26(6B2) ; also on sheet 12
RX_8: U2.25(7B2) ; also on sheet 12
SoC_I2C0_SCL: J1.E1 U1.6(SCL)
SoC_I2C0_SDA: J1.E2 U1.5(SDA)
SOC_SPI1_CLK: J1.C1 U17.15(A4)
SOC_SPI1_CLK_HDR: J9.5 U17.35(4B1)
SOC_SPI1_CLK_SE/LED: U17.32(4B2) U26.3(SCLK) ; also on sheet 9
SOC_SPI1_CS0: J1.D1 U17.10(A3)
SOC_SPI1_CS0_HDR: J9.7 U17.41(3B1)
SOC_SPI1_CS0_SE: U17.38(3B2) ; also on sheet 9
SOC_SPI1_CS1: J1.D2 U17.8(A2)
SOC_SPI1_CS1_HDR: J9.9 U17.42(2B1)
SOC_SPI1_MISO: J1.B1 U17.2(A0)
SOC_SPI1_MISO_HDR: J9.1 U17.48(0B1)
SOC_SPI1_MISO_SE: U17.45(0B2) ; also on sheet 9
SOC_SPI1_MOSI: J1.B2 U17.4(A1)
SOC_SPI1_MOSI_HDR: J9.3 U17.47(1B1)
SOC_SPI1_MOSI_LED: U17.44(1B2) U26.2(SIN)
TX_1: U4.45(0B2) ; also on sheet 11
TX_2: U4.44(1B2) ; also on sheet 11
TX_3: U4.39(2B2) ; also on sheet 11
TX_4: U4.38(3B2) ; also on sheet 11
TX_5: U4.32(4B2) ; also on sheet 12
TX_6: U4.31(5B2) ; also on sheet 12
TX_7: U4.26(6B2) ; also on sheet 12
TX_8: U4.25(7B2) ; also on sheet 12
N17188199: J11.2 R72.2
N17189922: R73.1 U26.23(IREF)
N17190440: LD1.2(ANODE) R64.2
N17190442: LD1.1(CATHODE) Q1.3(D)
N17190473: LD2.2(ANODE) R65.2
N17190482: LD2.1(CATHODE) Q2.3(D)
N17190504: LD5.1(CATHODE) Q3.3(D)
N17190506: LD5.2(ANODE) R68.2
N17190525: Q3.1(G) R71.2
N17190539: LD4.2(ANODE) R67.2
N17190541: LD3.2(ANODE) R66.2

Not connected (* = marked no-connect by the designer): J1 A26* A30* B29* C27* C28* D23* D27* D28* E23* E27*; J9 11* 13* 15* 17* 19*; U2 14(NC)*; U4 14(NC)*; U7 14(NC)*; U9 14(NC)*; U11 14(NC)*; U12 14(NC)* 23(A7)* 25(7B2)* 28(7B1)*; U17 14(NC)* 17(A5)* 21(A6)* 23(A7)* 25(7B2)* 26(6B2)* 28(7B1)* 29(6B1)* 31(5B2)* 34(5B1)*; U26 22(SOUT)*

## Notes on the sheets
sheet 1
- HARDWARE SCHEMATICS
- RUBBER FEET
- WASHER's
- ASSEMBLY NOTES
- 1. All MSL components should be baked as per JEDEC standard.
  2. PCB should be baked at 120 degree for 8 hours.
  3. Board assembly must comply with workmanship standards.
  IPC-A-610 Class 2, unless otherwise specified.
  4. These assemblies are ESD sensitive, ESD precautions
  shall be observed.
  5. These assemblies must be clean and free from flux and
  all contaminants. Use of no clean flux is not acceptable.
  6. Provide serial numbers to the assembled boards for identification.
  7. The assembled board are wrapped in ESD Covers(individual) and
  packed securely before shipment.
- STANDOFFs
- SCREWS
- 9mm Male to female Hex Standoff
- 40mm Male to female Standoffs for Foot Rests
- mounted near HSE and ADC mating connector
- LABELS
- 6mm Female to Female Standoffs mounted between supporting metal Plate and PCB
- Board Serial No.
- ORDERABLE PART NO
- Orderable part number
- Assembly Revision
- Variant
- Label Text
- 001
- TMDS64DC01EVM
- Metal Plate for supporting IO Link M12 Connector
- 002
- TMDS243DC01EVM
- Used with 9mm Standoff for
- Board to Board to Mating
- Used to Mount 40mm Foot rests
- BARE PCB
- Assembled PCB
- FIDUCIALS
- LOGOs
- LOGOs
- For Evaluation only; not FCC approved for resale
- Texas Intruments
- WEEE Mark
- CE Mark
sheet 2
- IO LINK/BREAKOUT BOARD
- TMDS64DC01EVM/TMDS243DC01EVM
- TABLE OF CONTENTS
- PAGE
- CONTENTS
- REV
- A
- 1
- TABLE OF CONTENTS
- VER
- 1.0
- 2
- REVISION HISTORY
- 3
- BLOCK DIAGRAM
- 4
- HSE CONNECTOR
- 5
- PRG SIGNALS
- 6
- GPMC & PERIPHERAL_COMMUNICATION_SIGNALS
- 7
- LED'S
- 8
- IO LINK TRANCIEVER[1:4]
- 9
- IO LINK TRANCIEVER[5:8]
- 10
- SMART SWITCH
- 11
- POWER AND ADC SECTION
- 12
- HARDWARE SCHEMATIC
sheet 3
- REVISION HISTORY
- REV #
- VER #
- DATE
- DESCRIPTION OF CHANGES
- AUTHOR
- REVIEWED  BY
- APPROVED  BY
- A
- 0.1
- 09-06-2021
- Mistral Design Team
- RAKESH RAJDEV
- AJIT MB
- Schmeatic Imported from REV E1
- Added Diode at Base of transistor for Voltage Spike Protection on TX line of IO Link PHY
  Changed Resistors R78 R79 R84 R85 R90 R91 R96 R97 to 240E
  Baselined
- A
- 1.0
- 09-06-2021
- Mistral Design Team
- RAKESH RAJDEV
- AJIT MB
sheet 4
- BLOCK DIAGRAM
sheet 5
- HSE CONNECTOR
- Off Page Connections
- I2C address: 0x52h
sheet 6
- PRG SIGNALS
- Off Page Connections
sheet 7
- GPMC SIGNALS
- Off Page Connections
- PERIPHERAL_COMMUNICATION_SIGNALS
sheet 8
- LED'S
- MUX SELECTION
- PRG0 & POWER_LED
- SEL
- INPUT/OUTPUT
- FUNCTION
- An
- HEADER SIDE IS
- L
- nB1
- An=nB1
- ACTIVATED
- IO LINK IS
- H
- nB2
- An=nB2
- ACTIVATED
- Off Page Connections
- Test Points
